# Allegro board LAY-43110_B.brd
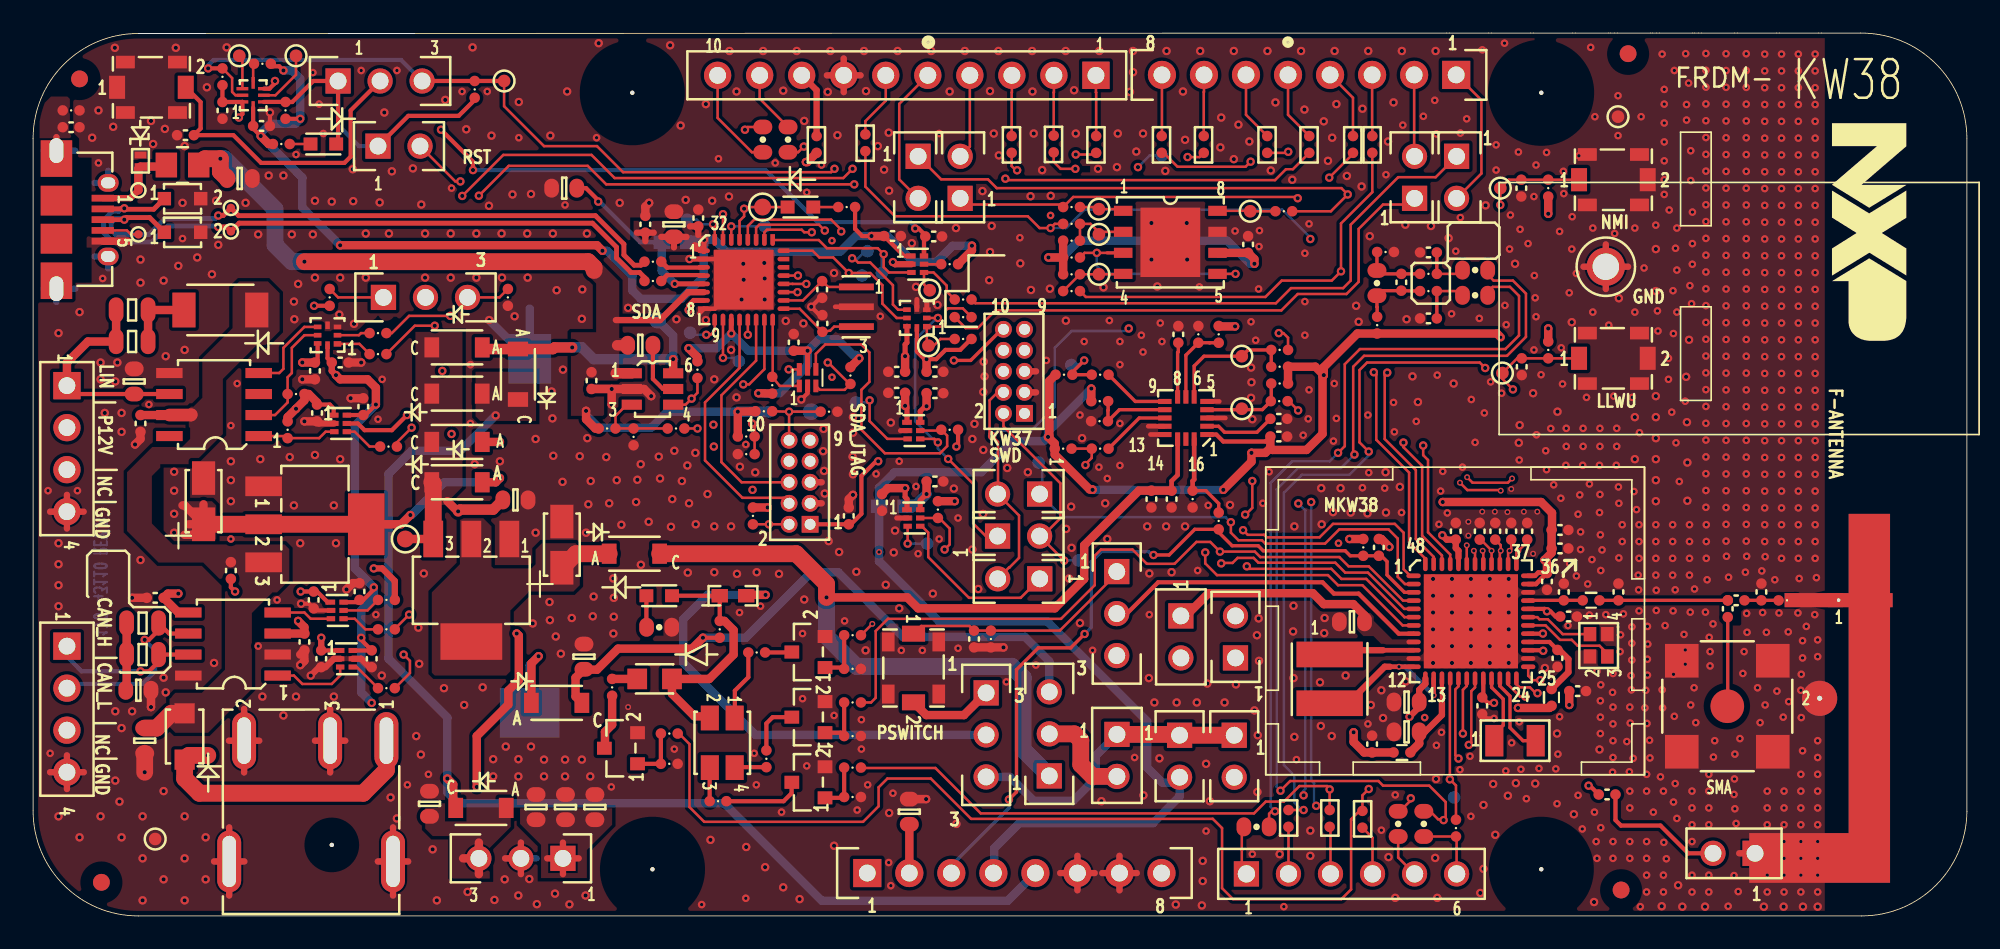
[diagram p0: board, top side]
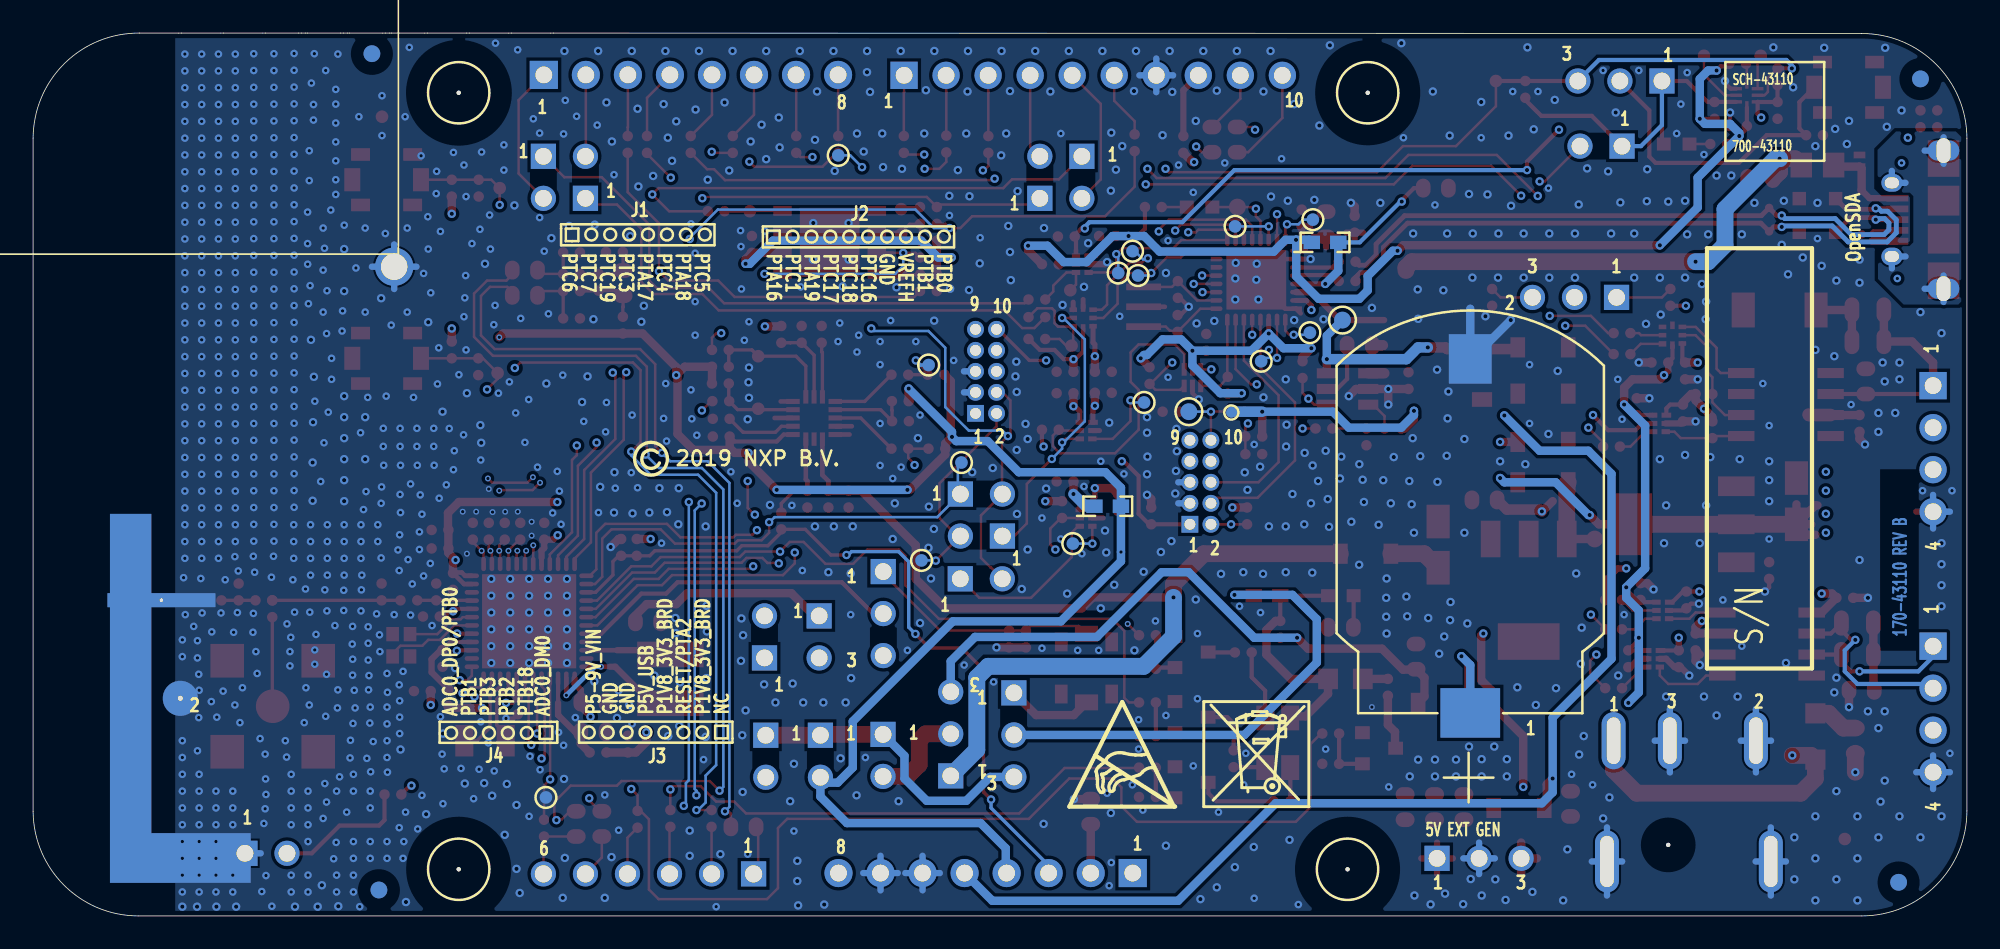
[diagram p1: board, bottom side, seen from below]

Outline 116.85 x 53.37 mm; copper layers: TOP, GND, INT_1, BOTTOM. Coordinates in mm from the lower left corner of the outline.
Outline path: 0,46.99 arc(1.86,51.48) 6.35,53.34 85.41,53.37 arc(85.49,53.37) 85.57,53.36 87.95,53.37 arc(88.03,53.37) 88.11,53.36 90.49,53.37 arc(90.57,53.37) 90.65,53.36 93.03,53.37 arc(93.11,53.37) 93.19,53.36 95.19,53.37 arc(95.24,53.37) 95.3,53.37 95.57,53.37 arc(95.65,53.37) 95.73,53.36 97.73,53.37 arc(97.78,53.37) 97.84,53.37 98.11,53.37 arc(98.19,53.37) 98.27,53.36 100.27,53.37 arc(100.32,53.37) 100.38,53.37 100.65,53.37 arc(100.73,53.37) 100.81,53.36 102.81,53.37 arc(102.89,53.37) 102.97,53.36 105.35,53.37 arc(105.43,53.37) 105.51,53.36 107.89,53.37 arc(107.97,53.37) 108.05,53.36 110.43,53.37 arc(114.96,51.53) 116.85,47.02 116.85,6.3 arc(114.97,1.84) 110.5,0 6.35,0 arc(1.86,1.86) 0,6.35 0,46.99

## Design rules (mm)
constraint set DEFAULT: min track width 0.152
net group DIFFPAIR0: nets SDA_USB_CONN_DN SDA_USB_CONN_DP
net group GA[0:7]: nets N21328439 N21328458
net group USB_SI_D: nets SDA_USB_DN SDA_USB_DP
net group CLOCKS: nets SDA_EXTAL SWD_CLK_TGTMCU SWD_CLK_TGTMCU_BUF
net group POW: nets P5V0_SDA_USB_CONN_VBUS
nets with their own width: min track width 0.254; nets GND
nets with their own width: min track width 0.508; nets P3V3_SDA P5-9V_VIN P5-9V_VIN_VR

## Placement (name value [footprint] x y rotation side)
ANT1  F_Antenna  [F_ANTENNA_DIG528-2]  109.1 19.09 270 top
BT1  S8421-45R  [BATTERY_HOLDER_2032_SM]  30.01 25.17 180 bottom
C1  0.1uF  [CC0402_25]  11.44 48.69 270 top
C2  1000pF  [CC0402_25]  2.3 47.68 0 top
C3  0.1uF  [CC0402_25]  13.8 47.75 0 top
C4  1000pF  [CC0402_25]  9.21 47.19 180 top
C5  10uF  [CC0603_OV]  12.48 44.58 0 top
C6  2.2uF  [CC0603_OV]  32.09 43.99 180 top
C7  1000pF  [CC0402_25]  89.93 43.99 270 top
C8  0.1uF  [CC0402_25]  40.2 42.19 90 top
C9  0.1uF  [CC0402_25]  37 41.81 90 top
C10  10uF  [CC0603_OV]  38.72 41.81 90 top
C11  0.1uF  [CC0402_25]  51.93 41.1 0 top
C12  0.1uF  [CC0402_25]  54.42 41.07 0 top
C13  0.1uF  [CC0402_25]  73.42 40.59 90 top
C14  220PF  [CC0402_25]  84.32 40.11 180 top
C15  0.1uF  [CC0402_25]  82.68 38.3 90 top
C16  22PF  [CC0402_25]  47.68 37.86 270 top
C17  220PF  [CC0402_25]  84.32 36.12 180 top
C18  22PF  [CC0402_25]  47.7 35.81 90 top
C19  0.1uF  [CC0402_25]  69.2 35.15 90 top
C20  0.1uF  [CC0402_25]  45.96 34.67 90 top
C21  18PF  [CC0603_OV]  36.69 34.49 0 top
C22  0.1uF  [CC0402_25]  18.55 33.45 0 top
C23  1000pF  [CC0402_25]  89.95 33.2 270 top
C24  0.1uF  [CC0402_25]  17.03 32.94 270 top
C25  0.1uF  [CC0402_25]  52.18 32.89 180 top
C26  0.1uF  [CC0402_25]  54.5 32.89 0 top
C27  0.1uF  [CC0402_25]  33.74 32.36 270 top
C28  220PF  [CC0603_OV]  6.11 32.31 90 top
C29  0.1uF  [CC0402_25]  52.18 31.62 180 top
C30  0.1uF  [CC0402_25]  54.5 31.6 0 top
C31  0.1uF  [CC0402_25]  19.95 30.78 90 top
C32  0.1uF  [CC0402_25]  17.16 30.4 270 top
C33  0.1uF  [CC0402_25]  6.49 29.77 270 top
C34  0.1uF  [CC0402_25]  75.27 30.05 0 top
C35  0.1uF  [CC0402_25]  75.27 28.98 0 top
C36  0.1uF  [CC0402_25]  56.86 16.74 270 top
C37  0.1uF  [CC0402_25]  54.5 26.26 0 top
C38  4.7uF  [CC0402_25]  67.58 25.2 270 top
C39  0.1uF  [CC0402_25]  68.8 25.2 270 top
C40  10uF  [CC0603_OV]  29.15 25.15 0 top
C41  10UF  [CC3216]  10.3 25.07 90 top
C42  0.1uF  [CC0402_25]  51.3 24.99 270 top
C43  0.1uF  [CC0402_25]  49.29 24.18 90 top
C44  0.1uF  [CC0402_25]  85.97 23.25 90 top
C45  10UF  [CC3216]  31.95 22.44 90 top
C46  12PF  [CC0402_25]  91.48 20.22 270 top
C47  0.1uF  [CC0402_25]  81.32 22.28 90 top
C48  0.1uF  [CC0402_25]  11.95 20.88 270 top
C49  0.1uF  [CC0402_25]  19.72 19.61 90 top
C50  0.6pF  [CC0402_25]  92.49 19.58 90 top
C51  0.3pF  [CC0402_25]  95.8 19.58 90 top
C52  10PF  [CC0402_25]  104.43 19.58 90 top
C53  0.1uF  [CC0402_25]  7.38 19.23 180 top
C54  0.1uF  [CC0402_25]  16.95 19.1 270 top
C55  10PF  [CC0402_25]  102.91 19.08 0 top
C56  10uF  [CC0603_OV]  33.29 15.67 90 top
C57  10PF  [CC0402_25]  102.4 18.57 270 top
C58  10uF  [CC0603_OV]  79.69 17.78 180 top
C59  0.1uF  [CC0402_25]  16.4 16.56 270 top
C60  0.1uF  [CC0402_25]  93.33 13.59 0 top
C61  0.1uF  [CC0402_25]  17.41 15.54 270 top
C62  0.1uF  [CC0402_25]  20.46 15.54 270 top
C63  4700PF  [CC0603_OV]  6.36 13.64 180 top
C64  10uF  [CC0603_OV]  82.99 12.93 180 top
C65  0.1uF  [CC0402_25]  87.57 12.7 270 top
C66  10uF  [CC0603_OV]  82.99 11.13 180 top
C67  1uF  [CC0402_25]  80.91 10.39 90 top
C68  10uF  [CC0603_OV]  6.74 10.59 270 top
C69  1uF  [CC0402_25]  92.11 15.57 270 top
C70  10PF  [CC0402_25]  95.11 7.34 180 top
C71  10uF  [CC0603_OV]  23.95 6.78 90 top
C72  10uF  [CC0603_OV]  30.39 6.58 90 top
C73  10uF  [CC0603_OV]  32.17 6.58 90 top
C74  10uF  [CC0603_OV]  33.95 6.58 90 top
C75  2.2uF  [CC0603_OV]  52.95 6.3 90 top
C78  12PF  [CC0402_25]  92.79 18.1 0 top
C79  3pF  [CC0402_25]  90.28 23.25 90 top
C80  3pF  [CC0402_25]  89.32 23.25 90 top
C81  3pF  [CC0402_25]  88.35 23.25 90 top
C82  3pF  [CC0402_25]  87.41 23.25 90 top
C86  1uF  [CC0402_25]  92.27 23.33 0 top
C87  0.1uF  [CC0402_25]  92.27 22.21 0 top
D1  YEL-GRN  [LED_0603]  46.37 42.85 180 top
D2  PMEG3050EP  [SOD-128]  11.32 36.63 180 top
D3  RB160M-30  [PMDU_SOD123]  25.62 34.37 0 top
D4  RB160M-30  [PMDU_SOD123]  29.3 32.74 90 top
D5  RB160M-30  [PMDU_SOD123]  25.62 31.57 0 top
D6  RB160M-30  [PMDU_SOD123]  25.62 28.65 0 top
D8  RB160M-30  [PMDU_SOD123]  36.33 21.89 180 top
D10  RB160M-30  [PMDU_SOD123]  31.64 12.88 180 top
D11  PNS40010ER  [SOD123W]  9.16 10.85 270 top
D12  RB160M-30  [PMDU_SOD123]  27.06 6.53 0 top
D13  RB160M-30  [PMDU_SOD123]  25.62 26.21 0 top
D14  PESD5V0S1UL  [SOD-882]  6.49 45.64 90 top
D15  PESD5V0S1BA  [SOD323_BID]  9.03 41.33 0 top
D16  PESD5V0S1BA  [SOD323_BID]  9.03 43.36 0 top
J1  SKT_1X8  [CON_1X8_SKT_2P54_TH]  85.99 50.84 270 top
J2  SKT_1X10  [CON_SKT1X10_TH]  64.22 50.81 270 top
J3  SKT_1X8  [CON_1X8_SKT_2P54_TH]  50.41 2.59 90 top
J4  SKT_1X6  [CON_SKT1X6_TH]  73.32 2.54 90 top
J5  HDR_1X3  [HDR103]  18.43 50.47 90 top
J6  HDR 1X2 TH  [SH_HDR102_BOTTOM]  20.84 46.53 90 top
J7  HDR 1X2 TH  [SH_HDR102_BOTTOM]  53.48 45.92 0 top
J8  HDR 1X2 TH  [SH_HDR102_BOTTOM]  86.02 45.92 0 top
J9  HDR 1X2 TH  [SH_HDR102_BOTTOM]  56.02 43.38 180 top
J10  HDR 1X2 TH  [SH_HDR102_BOTTOM]  83.48 43.38 180 top
J11  USB AB 5  [CON9_MICROAB_USB_SHELL_TH]  1.41 42.09 270 top
J12  HDR 2X5  [HDR_2X5_6X3_1P27MM_TH]  59.91 30.38 90 top
J13  HDR 1X4 RA  [CON_HDR_4M_100_TH_RA]  2.04 32.05 270 top
J14  HDR 2X5  [HDR_2X5_6X3_1P27MM_TH]  46.95 23.67 90 top
J15  HDR 1X2 TH  [SH_HDR102_BOTTOM]  60.82 25.5 270 top
J16  HDR 1X2 TH  [SH_HDR102_BOTTOM]  58.28 22.96 90 top
J17  HDR 1X2 TH  [SH_HDR102_BOTTOM]  60.83 20.38 270 top
J21  SLE-100010072-F01  [CON5_SMA_7SQ_SM]  102.37 12.67 0 top
J23  HDR 1X4 RA  [CON_HDR_4M_100_TH_RA]  2.04 16.31 270 top
J24  HDR_1X3  [HDR103]  57.59 13.48 0 top
J27  HDR_1X2  [HDR_1X2_2P54MM]  65.49 10.97 0 top
J28  HDR 1X2 TH  [SH_HDR102_BOTTOM]  69.28 10.92 0 top
J29  HDR 1X2 TH  [SH_HDR102_BOTTOM]  72.58 10.92 0 top
J30  HDR_1X2  [HDR_1X2_2P54MM]  69.35 18.14 0 top
J31  HDR 1X2 TH  [SH_HDR102_BOTTOM]  72.66 15.6 180 top
J32  CON PWR 3  [CON3_PWR_JACK_TH_PJ051A]  21.35 10.59 90 top
J33  HDR_1X2  [HDR_1X2_2P54MM]  104.05 3.78 270 top
J34  HDR_1X3  [HDR103]  32.02 3.48 270 top
J35  HDR_1X3  [HDR103]  61.4 8.46 180 top
J38  HDR_1X3  [HDR103]  65.48 20.82 0 top
J39  HDR_1X3  [HDR103]  21.17 37.39 90 top
L1  330 OHM  [IND_0805]  9.03 45.39 0 top
L2  0.0047uH  [IND_0402]  94.15 19.08 0 top
L3  10uH  [IND_VLS4012E]  78.34 14.33 270 top
L4  0.1uH  [IND_0402]  91.76 13.21 90 top
L5  0.1uH  [IND_0402]  82.72 9.88 180 top
LED1  RED  [LED_0603]  17.54 46.66 0 top
LED2  YEL-GRN  [LED_0603]  37.83 19.35 180 top
LED3  RED  [LED_2P_0805]  37.55 14.33 0 top
LED4  CLV1A-FKB-CK1vw1de1BB7C3C3  [LED4_3P4X3MM_SMT]  41.64 10.46 0 top
NOREF  -  []  49.09 55.07 90 top
NOREF#2  -  []  91.35 15.56 90 top
NOREF#3  -  []  84.5 14.31 0 top
NOREF#4  -  []  101.87 1.95 90 top
NOREF#5  -  []  71.16 28.6 90 top
NOREF#6  -  []  84.65 15.06 0 top
NOREF#7  -  []  86.5 16.31 90 top
NOREF#8  -  []  5 48.44 0 top
NOREF#9  -  []  85.4 59.9 90 top
NOREF#10  -  []  76.57 12.28 90 top
NOREF#11  -  []  365.6 -149.21 0 top
NOREF#12  -  []  93.42 33.71 0 top
NOREF#13  -  []  42.75 10.35 90 top
NOREF#14  -  []  96.14 9.48 0 top
NOREF#15  -  []  102.64 10.48 90 top
NOREF#16  -  []  91.35 15.06 90 top
NOREF#17  -  []  91.35 15.06 90 top
NOREF#18  -  []  37.1 3.48 0 top
NOREF#19  -  []  59.98 38.09 90 top
NOREF#20  -  []  53.58 12.49 90 top
NOREF#21  -  []  78.24 12.86 90 top
NOREF#22  -  []  86.5 17.31 90 top
NOREF#23  -  []  97.14 10.48 0 top
NOREF#24  -  []  26.7 49.62 90 top
NOREF#25  -  []  46.95 23.67 90 top
NOREF#26  -  []  51.68 13.41 0 top
NOREF#27  -  []  46.49 0.94 90 top
NOREF#28  -  []  86.96 43.48 90 top
NOREF#29  -  []  39.17 24.31 90 top
NOREF#30  -  []  52.16 43.48 0 top
NOREF#31  -  []  93.42 39.42 0 top
NOREF#32  -  []  86.25 14.46 0 top
NOREF#33  -  []  76.19 12.66 0 top
NOREF#34  -  []  35.17 24.31 0 top
NOREF#35  -  []  46.24 19.2 0 top
NOREF#36  -  []  20.44 25.64 0 top
NOREF#37  -  []  21.49 25.64 90 top
NOREF#38  -  []  91.5 14.31 90 top
NOREF#39  -  []  46.95 23.67 90 top
NOREF#40  -  []  11.19 19.95 0 top
NOREF#41  -  []  54.85 9.54 90 top
NOREF#42  -  []  97.07 37.9 90 top
NOREF#43  -  []  173.86 59.85 0 top
NOREF#44  -  []  84.65 15.06 0 top
NOREF#45  -  []  69.66 31.37 0 top
NOREF#46  -  []  14.49 15.45 90 top
NOREF#47  -  []  85.4 59.9 0 top
NOREF#48  -  []  93.92 37.9 0 top
NOREF#49  -  []  -14.33 -140.12 90 top
NOREF#50  -  []  37.1 3.48 0 top
NOREF#51  -  []  26.94 3.48 0 top
NOREF#52  -  []  93.92 32.18 0 top
NOREF#53  -  []  86.63 21.27 0 top
NOREF#54  -  []  86.88 17.81 0 top
NOREF#55  -  []  48.22 55.07 0 top
NOREF#56  -  []  11.04 20.75 0 top
NOREF#57  -  []  83.1 44.9 90 top
NOREF#58  -  []  92.8 0.01 90 top
NOREF#59  -  []  27.13 49.52 90 top
NOREF#60  -  []  20.53 25.86 0 top
NOREF#61  -  []  6.18 44.51 90 top
NOREF#62  -  []  93.34 32.06 0 top
NOREF#63  -  []  85.93 31.51 0 top
NOREF#64  -  []  17.02 47.69 90 top
NOREF#65  -  []  86.25 14.46 0 top
NOREF#66  -  []  25.52 9.32 90 top
NOREF#67  -  []  59.91 30.38 90 top
NOREF#68  -  []  390.58 -149.21 0 top
NOREF#69  -  []  85.25 14.46 0 top
NOREF#70  -  []  48.13 54.85 0 top
NOREF#71  -  []  68.16 28.6 0 top
NOREF#72  -  []  30.01 12.27 90 top
NOREF#73  -  []  40.14 3.62 0 top
NOREF#74  -  []  93.17 64.32 0 top
NOREF#75  -  []  52.84 15.13 90 top
NOREF#76  -  []  90.38 14.31 90 top
NOREF#77  -  []  68.16 28.61 0 top
NOREF#78  -  []  97.07 32.18 90 top
NOREF#79  -  []  23.41 12.43 90 top
NOREF#80  -  [unnamed#2]  4.13 2.03 90 top
NOREF#81  -  []  50.55 9.54 0 top
NOREF#82  -  []  85.64 44.91 90 top
NOREF#83  -  []  24.2 10.74 90 top
NOREF#84  -  []  93.44 44.98 0 top
NOREF#85  -  []  102.29 7.46 0 top
NOREF#86  -  []  83.42 17.56 90 top
NOREF#87  -  []  35.42 25.81 0 top
NOREF#88  -  []  27.15 49.84 90 top
NOREF#89  -  []  87.06 38.09 90 top
NOREF#90  -  []  97.67 43.33 90 top
NOREF#91  -  []  0 41.92 0 top
NOREF#92  -  []  93.34 32.06 0 top
NOREF#93  -  []  85.25 14.46 0 top
NOREF#94  -  []  68.38 29.1 90 top
NOREF#95  -  []  14.64 15.15 90 top
NOREF#96  -  []  13.14 48.82 90 top
NOREF#97  -  []  44.07 3.54 0 top
NOREF#98  -  []  93.37 43.33 0 top
NOREF#99  -  []  70.93 31.1 90 top
NOREF#100  -  []  6.49 45.29 90 top
NOREF#101  -  []  97.64 32.06 90 top
NOREF#102  -  []  9.3 48.44 90 top
NOREF#103  -  []  86.5 16.31 90 top
NOREF#104  -  []  95.07 61.52 90 top
NOREF#105  -  []  -14.33 -113.45 0 top
NOREF#106  -  []  9.49 50.34 0 top
NOREF#107  -  []  30.01 12.43 90 top
NOREF#108  -  []  47.92 22.91 0 top
NOREF#109  -  []  53.2 12.91 90 top
NOREF#110  -  []  97.07 32.18 90 top
NOREF#111  -  []  90.75 14.46 90 top
NOREF#112  -  []  86.5 17.31 90 top
NOREF#113  -  [unnamed#2]  96.38 52.12 90 top
NOREF#114  -  []  6.18 44.51 0 top
NOREF#115  -  []  13.72 51.99 0 top
NOREF#116  -  []  49.18 54.85 90 top
NOREF#117  -  []  97.09 43.46 90 top
NOREF#118  -  []  22.11 17.16 0 top
NOREF#119  -  []  5.58 48.56 0 top
NOREF#120  -  []  60.87 23.02 90 top
NOREF#121  -  []  44.84 0.36 90 top
NOREF#122  -  []  45.68 23.67 0 top
NOREF#123  -  []  93.94 43.46 0 top
NOREF#124  -  []  101.37 16.29 0 top
NOREF#125  -  []  86.75 59.7 90 top
NOREF#126  -  []  93.42 33.71 0 top
NOREF#127  -  []  60.87 29.62 0 top
NOREF#128  -  []  99.23 1.95 0 top
NOREF#129  -  []  5.89 -36.7 0 top
NOREF#130  -  []  44.12 15.23 90 top
NOREF#131  -  []  108.7 47.9 270 top
NOREF#132  -  []  27.15 50.64 90 top
NOREF#133  -  []  8.73 48.56 90 top
NOREF#134  -  []  58.64 30.38 0 top
NOREF#135  -  []  93.92 42.98 0 top
NOREF#136  -  []  68.38 31.1 0 top
NOREF#137  -  []  93.92 32.18 0 top
NOREF#138  -  []  95.26 6.02 0 top
NOREF#139  -  []  47.92 16.31 90 top
NOREF#140  -  []  -359.49 185.27 0 top
NOREF#141  -  []  21.4 25.86 90 top
NOREF#142  -  []  54.8 43.48 90 top
NOREF#143  -  []  14.49 15.45 90 top
NOREF#144  -  []  -82.26 -259.56 0 top
NOREF#145  -  []  93.42 44.5 0 top
NOREF#146  -  []  97.64 42.85 90 top
NOREF#147  -  []  5.08 50.09 0 top
NOREF#148  -  []  84.42 38.09 0 top
NOREF#149  -  []  52.36 19.2 0 top
NOREF#150  -  []  93.34 42.85 0 top
NOREF#151  -  []  43.19 0.94 0 top
NOREF#152  -  []  97.07 42.98 90 top
NOREF#153  -  []  84.32 43.48 0 top
NOREF#154  -  []  43.59 0.41 0 top
NOREF#155  -  []  46.71 3.54 90 top
NOREF#156  -  []  59.91 30.38 90 top
NOREF#157  -  []  42.8 16.65 90 top
NOREF#158  -  []  22.88 9.32 0 top
NOREF#159  -  []  97.64 32.06 90 top
NOREF#160  -  []  69.16 28.82 90 top
NOREF#161  -  []  51.68 13.41 90 top
NOREF#162  -  []  38.82 10.44 90 top
NOREF#163  -  []  41.48 15.23 0 top
NOREF#164  -  []  50.94 12.49 0 top
NOREF#165  -  []  381.86 -165.18 0 top
NOREF#166  -  []  -385.52 -339.88 0 top
NOREF#167  -  []  103.64 9.48 90 top
NOREF#168  -  []  50.2 15.13 0 top
NOREF#169  -  []  57.34 38.09 0 top
NOREF#170  -  []  30.01 12.27 90 top
NOREF#171  -  [unnamed#2]  2.81 50.6 90 top
NOREF#172  -  []  42.78 3.62 90 top
NOREF#173  -  []  84.5 14.31 0 top
NOREF#174  -  []  93.34 37.77 0 top
NOREF#175  -  []  68.38 30.6 90 top
NOREF#176  -  []  90.75 14.46 90 top
NOREF#177  -  []  56.02 44.9 90 top
NOREF#178  -  []  97.64 37.77 90 top
NOREF#179  -  []  68.38 30.6 90 top
NOREF#180  -  []  9.99 48.82 0 top
NOREF#181  -  []  91.35 15.56 90 top
NOREF#182  -  []  86.88 17.81 90 top
NOREF#183  -  [unnamed#2]  95.96 1.57 90 top
NOREF#184  -  []  86.63 21.27 0 top
NOREF#185  -  []  53.48 44.91 90 top
NOREF#186  -  []  83.38 14.31 0 top
NOREF#187  -  [unnamed#2]  95.96 1.57 90 bottom
NOREF#188  -  [unnamed#2]  4.13 2.03 90 bottom
NOREF#189  -  []  79.51 27.61 180 bottom
NOREF#190  -  []  77.09 5.51 180 bottom
NOREF#191  -  [unnamed#2]  36.21 49.76 180 bottom
NOREF#192  -  []  77.14 12.88 180 bottom
NOREF#193  -  [unnamed#2]  91.14 2.82 180 bottom
NOREF#194  -  [unnamed#2]  96.38 52.12 90 bottom
NOREF#195  -  [unnamed#2]  91.14 49.76 180 bottom
NOREF#196  -  []  128.76 -52.14 270 bottom
NOREF#197  -  [unnamed#2]  37.43 2.82 180 bottom
NOREF#198  -  []  9.36 14.96 90 bottom
NOREF#199  -  []  54.22 6.6 180 bottom
NOREF#200  -  []  46.11 6.6 180 bottom
NOREF#201  -  []  114.3 39.52 180 bottom
NOREF#202  -  [unnamed#2]  2.81 50.6 90 bottom
Q1  BSH111BK  [SOT23_A]  46.85 15.95 90 top
Q2  BSH111BK  [SOT23_A]  46.85 12.01 90 top
Q3  BSH111BK  [SOT23_A]  46.85 8.08 90 top
Q4  BSH111BK  [SOT23_A]  35.52 10.13 90 top
R1  4.7K  [RC0402_25]  13.86 51.51 0 top
R2  180K  [RC0402_25]  11.44 50.72 90 top
R3  0  [RC0402_25]  26.68 49.96 90 top
R4  100  [RC0402_25]  2.3 48.69 0 top
R5  10K  [RC0402_25]  15.25 48.69 90 top
R6  0  [RC0603_OV]  44.09 46.93 90 top
R7  0  [RC0603_OV]  45.62 46.93 90 top
R8  680  [RC0402_25]  15 46.66 0 top
R9  10K  [RC0402_25]  91.55 43.99 90 top
R10  270  [RC0402_25]  49.16 42.85 180 top
R11  0  [RC0402_25]  62.75 42.85 0 top
R12  0  [RC0402_25]  75.58 42.6 0 top
R13  0  [RC0402_25]  62.75 41.83 0 top
R14  10K  [RC0402_25]  62.75 40.82 0 top
R15  4.99K  [RC0402_25]  81.72 40.13 0 top
R16  4.7K  [RC0402_25]  55.38 39.4 180 top
R17  10K  [RC0402_25]  62.75 39.8 0 top
R18  33  [RC0402_25]  37.45 39.55 0 top
R19  0  [RC0603_OV]  87.13 39.04 180 top
R20  100  [RC0402_25]  84.32 38.81 0 top
R21  10K  [RC0402_25]  62.75 38.79 0 top
R22  33  [RC0402_25]  37.45 38.38 0 top
R23  0  [RC0402_25]  62.75 37.77 180 top
R24  100  [RC0402_25]  84.32 37.77 0 top
R25  0  [RC0603_OV]  87.13 37.52 180 top
R26  1K  [RC0402_25]  56.2 37.26 0 top
R27  2K  [RC0805_OV]  5.98 36.63 0 top
R28  0  [RC0402_25]  20.84 35.23 0 top
R29  1K  [RC0402_25]  56.2 36.2 180 top
R30  4.99K  [RC0402_25]  81.22 35.71 90 top
R31  0  [RC0402_25]  70.41 35.15 90 top
R32  10K  [RC0402_25]  71.64 35.15 270 top
R33  10K  [RC0402_25]  56.2 34.87 180 top
R34  2K  [RC0805_OV]  5.98 34.72 0 top
R35  0  [RC0402_25]  20.84 33.96 0 top
R36  10K  [RC0402_25]  91.55 34.21 270 top
R37  0  [RC0402_25]  75.32 34.21 0 top
R38  10K  [RC0402_25]  40.14 33.02 270 top
R39  10.0K  [RC0402_25]  62.29 32.72 0 top
R40  0  [RC0402_25]  64.48 32.72 180 top
R41  2.2K  [RC0402_25]  75.32 33.2 180 top
R42  10K  [RC0402_25]  49.39 32.66 270 top
R43  10K  [RC0402_25]  44.67 32.08 90 top
R44  2.2K  [RC0402_25]  75.32 32.18 180 top
R45  4.7K  [RC0402_25]  15.89 31.55 0 top
R46  10K  [RC0402_25]  64.45 31.12 0 top
R47  0  [RC0402_25]  75.3 31.12 0 top
R48  4.7K  [RC0402_25]  44.16 30.51 0 top
R49  10K  [RC0402_25]  48.09 30.48 0 top
R50  4.7K  [RC0402_25]  17.92 37.39 90 top
R51  0  [RC0402_25]  64.44 29.91 180 top
R52  10.0K  [RC0402_25]  34.68 29.46 0 top
R53  1K  [RC0402_25]  38.85 29.46 180 top
R54  4.7K  [RC0402_25]  15.38 29.39 90 top
R55  4.7K  [RC0402_25]  55.38 29.39 180 top
R56  4.7K  [RC0402_25]  43.09 28.98 0 top
R57  15K  [RC0402_25]  36.28 28.96 270 top
R58  0  [RC0402_25]  21.48 28.37 0 top
R60  10.0K  [RC0402_25]  62.24 28.24 0 top
R61  0  [RC0402_25]  64.48 28.24 180 top
R62  10.0K  [RC0402_25]  43.09 27.91 180 top
R63  102K  [RC0402_25]  57.87 16.74 270 top
R64  10K  [RC0402_25]  70.07 25.2 90 top
R65  4.7K  [RC0402_25]  54.67 24.56 270 top
R66  10K  [RC0402_25]  43.5 24.18 270 top
R67  0  [RC0402_25]  71.64 23.88 270 top
R69  10K  [RC0402_25]  80.38 22.28 270 top
R70  0  [RC0402_25]  41.49 17.32 270 top
R71  4.7K  [RC0402_25]  21.35 19.1 180 top
R72  0  [RC0402_25]  105.98 19.07 0 top
R73  60.4  [RC0805_OV]  6.62 17.7 180 top
R74  0  [RC0402_25]  21.35 17.32 0 top
R75  220  [RC0603_OV]  37.83 17.45 0 top
R76  0  [RC0402_25]  49.52 16.97 180 top
R77  60.4  [RC0805_OV]  6.62 15.8 0 top
R80  10K  [RC0402_25]  49.52 14.94 180 top
R81  0  [RC0402_25]  21.35 13.77 0 top
R82  0  [RC0402_25]  49.52 12.9 0 top
R85  10K  [RC0402_25]  49.52 10.87 0 top
R87  470  [RC0402_25]  43.73 15.93 180 top
R88  270  [RC0402_25]  34.99 13.82 90 top
R89  0  [RC0402_25]  49.52 8.97 0 top
R90  270  [RC0402_25]  44.31 9.5 270 top
R92  0  [RC0402_25]  38.44 11.02 180 top
R93  270  [RC0402_25]  41.39 6.93 180 top
R94  10K  [RC0402_25]  49.52 7.19 180 top
R96  0  [RC0603_OV]  82.49 5.56 270 top
R97  0  [RC0603_OV]  84.04 5.56 270 top
R98  10K  [RC0402_25]  38.44 9.19 180 top
R99  0  [RC0603_OV]  73.93 5.38 180 top
R100  0  [RC0402_25]  85.98 5.31 270 top
R101  4.7K  [RC0402_25]  28.69 37.39 270 top
RT1  10K  [RC0603_OV]  81.2 38.25 90 top
SH1  0  [SH0402]  50.29 46.74 90 top
SH2  0  [SH0402]  61.67 46.66 90 top
SH3  0  [SH0402]  47.35 46.63 90 top
SH4  0  [SH0402]  59.13 46.63 90 top
SH5  0  [SH0402]  64.24 46.63 90 top
SH6  0  [SH0402]  68.2 46.63 90 top
SH7  0  [SH0402]  70.74 46.63 90 top
SH8  0  [SH0402]  74.57 46.63 90 top
SH9  0  [SH0402]  77.11 46.63 90 top
SH10  0  [SH0402]  79.76 46.63 90 top
SH11  0  [SH0402]  80.92 46.63 90 top
SH12  0  [SH0603]  42.29 19.35 0 top
SH13  0  [SH0402]  75.86 5.89 270 top
SH14  0  [SH0402]  78.35 5.89 270 top
SH15  0  [SH0402]  80.33 5.84 270 top
SH16  0  [SH0603]  38.79 40.72 180 bottom
SH17  0  [SH0603]  51.92 24.77 180 bottom
SW1  TL1015AF160QG  [SW2_SPST_4X3_SM]  7.15 50.09 0 top
SW2  TL1015AF160QG  [SW2_SPST_4X3_SM]  95.49 44.5 0 top
SW3  TL1015AF160QG  [SW2_SPST_4X3_SM]  95.49 33.71 0 top
SW4  TL1015AF160QG  [SW2_SPST_4X3_SM]  53.2 14.99 270 top
TP1  -  [TPAD_030]  12.46 51.99 0 top
TP2  -  [TPAD_030]  15.89 51.99 0 top
TP3  -  [TPAD_030]  28.46 50.47 0 top
TP4  -  [TPAD_030]  95.77 48.31 0 top
TP5  -  [TPAD_020]  6.36 43.87 0 top
TP6  -  [TPAD_030]  88.66 43.99 0 top
TP7  -  [TPAD_020]  11.95 42.8 0 top
TP8  -  [TPAD_040]  44.08 42.85 0 top
TP9  -  [TPAD_030]  64.4 42.72 0 top
TP10  -  [TPAD_030]  73.55 42.6 0 top
TP11  -  [TPAD_030]  64.4 41.2 0 top
TP12  -  [TPAD_020]  11.95 41.38 0 top
TP13  -  [TPAD_020]  6.36 41.2 0 top
TP14  -  [TPAD_030]  64.4 38.79 0 top
TP15  -  [TPAD_030]  54.18 37.82 0 top
TP16  -  [TPAD_030]  54.1 34.47 0 top
TP17  -  [TPAD_030]  73.04 33.83 0 top
TP18  -  [TPAD_030]  88.79 32.82 0 top
TP19  TESTLOOP_BLACK  [TP_TH_063]  95.03 39.24 0 top
TP20  -  [TPAD_030]  73.04 30.66 0 top
TP21  -  [TPAD_040]  22.49 22.78 0 top
TP22  -  [TPAD_030]  68.2 45.97 180 bottom
TP23  -  [TPAD_030]  39.52 42.09 180 bottom
TP24  -  [TPAD_030]  44.22 41.68 180 bottom
TP25  -  [TPAD_030]  85.86 7.16 180 bottom
TP26  -  [TPAD_030]  50.09 38.71 180 bottom
TP27  -  [TPAD_030]  51.28 38.86 180 bottom
TP28  -  [TPAD_030]  50.42 40.18 180 bottom
TP29  -  [TPAD_040]  37.73 36.02 180 bottom
TP30  -  [TPAD_030]  39.7 35.26 180 bottom
TP31  -  [TPAD_030]  42.65 33.53 180 bottom
TP32  -  [TPAD_030]  62.74 33.3 180 bottom
TP33  -  [TPAD_030]  49.72 31.04 180 bottom
TP34  -  [TPAD_040]  47.02 30.48 180 bottom
TP35  -  [TPAD_020]  44.45 30.43 180 bottom
TP36  -  [TPAD_030]  60.76 27.41 180 bottom
TP37  -  [TPAD_030]  54.03 22.5 180 bottom
TP38  -  [TPAD_030]  63.17 21.49 180 bottom
TP39  -  [TPAD_030]  7.38 4.65 0 top
U1  NTSX2102GU8H  [XQFN8_1P45X1P25MM]  13.3 49.61 90 top
U3  AT45DB041E  [DFN8_1P27_6X5MM_3P6X4P2]  68.72 40.72 0 top
U4  74LVCH1T45  [UDFN6_1X1P5MM]  53.45 39.4 0 top
U5  MK20DX128VFM5  [QFN32_S142EP]  42.94 38.46 0 top
U6  74LVC2T45GM,125  [QFN8_1P6X1P6MM]  53.4 36.14 180 top
U7  74LVC2T45GM,125  [QFN8_1P6X1P6MM]  17.79 35.1 180 top
U8  NLX2G14  [UDFN6_1P45X1_0P5MM]  46.8 32.54 90 top
U9  MIC2005-0.8YM6  [SOT23-6_A]  37.43 31.85 0 top
U10  TJA1027T/20  [SO8_1P27_4X5]  10.93 30.91 180 top
U11  FXOS8700CQ  [QFN5X3_0P5_3X3]  69.66 30.1 180 top
U12  74LVCH1T45  [UDFN6_1X1P5MM]  18.58 29.77 0 top
U13  74LVCH1T45  [UDFN6_1X1P5MM]  53.23 29.34 0 top
U14  74LVCH1T45  [UDFN6_1X1P5MM]  53.23 24.05 0 top
U15  NCP1117ST50T3G  [SOT223]  17.03 23.67 270 top
U16  NCP1117ST33T3G  [SOT223]  26.48 19.69 180 top
U17  74LVCH1T45  [UDFN6_1X1P5MM]  18.38 18.47 0 top
U18  MKW38A512VFT4  [QFN_48_0P5_7X7_5P7EP]  86.88 17.81 0 top
U19  TJA1057GT/3  [SO8_1P27_4X5]  12.08 16.43 180 top
U20  74LVCH1T45  [UDFN6_1X1P5MM]  18.94 15.54 0 top
X1  8 MHz  [XTAL3_3P35X1P45_SM]  49.75 36.82 90 top
Y1  32MHz  [XTAL4_2P1X1P7MM_SM]  94.6 16.36 270 top
Y2  32.768 KHZ  [XTAL2-3P2X1P5-SM]  89.55 10.59 0 top

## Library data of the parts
ANT1 = F_Antenna
BT1 = BATTERY
C1-C20 C22-C40 C42-C44 C46-C51 C53 C54 C56 C58-C69 C71-C75 C78-C82 C86 C87 = CAP_NP
C21 C52 C55 C57 C70 = CAP_NP: tolerance: 5%
C41 C45 = CAP_POL
D1 LED1-LED3 = LED
D2-D6 D8 D10 D12 D13 = DIODE_SCHTKY
D11 = DIODE
D14 = DIODE_TVS
D15 D16 = DIODE_TVS_BIDIR
J1 J3 = CONN_HDR_8X1
J2 = CONN_HDR_10X1
J4 = CONN_HDR_6X1
J5 J24 J34 J35 J38 J39 = CONN_HDR_3X1
J6-J10 J15-J17 J27-J31 J33 = CONN_HDR_2X1
J11 = MICRO_USB_CONN_9PIN
J12 J14 = CONN_HDR_5X2
J13 J23 = CONN_HDR_4X1
J21 = CONN_COAX_1P_F
J32 = DC_POWER_JACK_SHD
L1 = BEAD
L2 L4 L5 = INDUCTOR
L3 = IND_FERRITE
LED4 = CLV1A_LED_4P
Q1-Q4 = NMOS_2N7002BKW_3P
R1 R9 R16 R20 R21 R24 R36 R39 R45 R48 R50 R52 R54-R56 R60 R65 R71 R101 = RES: tolerance: 1%
R2 R4-R8 R10-R15 R17-R19 R22 R23 R25-R35 R37 R38 R40-R44 R46 R47 R49 R51 R53 R57 R58 R61-R64 R66 R67 R69 R70 R72-R77 R80-R82 R85 R87-R90 R92-R94 R96-R100 = RES
R3 = RES: tolerance: 5%
RT1 = THERMISTOR: tolerance: 1%
SH1-SH17 = RES_SHORT-2
SW1-SW4 = SW_SPNO_2P_GND6P
TP1-TP39 = TESTLOOP
U1 = NTSX2102GD
U3 = AT45DB021E_9P
U4 U12-U14 U17 U20 = 74LVCH1T45_6P
U5 = PK20DX128V_QFN_32P
U6 U7 = 74LVC2T45GM_8P
U8 = NLX2G14_6P
U9 = MIC2005-0.8YM6
U10 = TJA1027T_8P
U11 = FXOS8700CQ_QFN_16P
U15 U16 = LD1117AS18
U18 = MKW38A512VFT4_QFN48
U19 = TJA1057GT3_8P
X1 = XTAL_CS
Y1 = XTAL_13
Y2 = XTAL

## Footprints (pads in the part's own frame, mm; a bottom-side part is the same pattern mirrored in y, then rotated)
BATTERY_HOLDER_2032_SM
  rect 3.607x2.997 smd: 1(0,-12.9)
  rect 2.591x2.997 smd: 2(0,8.5)
CC0402_25
  round 0.635 smd: 1(-0.508,0) 2(0.508,0)
CC0603_OV
  oval 0.889x1.143 smd: 1(-0.762,0) 2(0.762,0)
CC3216
  rect 2.032x1.397 smd: 1(-1.397,0) 2(1.397,0)
CON3_PWR_JACK_TH_PJ051A
  round 0.254 hole 2.54 unplated: (-6.3,3.3)
  oval 3.454x1.448 hole 2.819x0.813: 1(0,0) 2(0,8.6) 3(0,3.4)
  oval 3.734x1.448 hole 3.099x0.813: SH1(-7.3,9.5) SH2(-7.3,-0.4)
CON5_SMA_7SQ_SM
  round 2.032 smd: 1(0,0)
  rect 2.032x2.032 smd: 2(-2.75,-2.75) 3(2.75,-2.75) 4(2.75,2.75) 5(-2.75,2.75)
CON9_MICROAB_USB_SHELL_TH
  rect 1.803x1.905 smd: (-1.15,0) (1.15,0)
  rect 0.406x1.346 smd: 1(-1.3,2.8) 2(-0.65,2.8) 3(0,2.8) 4(0.65,2.8) 5(1.3,2.8)
  oval 1.067x1.27 hole 0.66x0.864: 6(2.225,3.125) 9(-2.225,3.125)
  rect 2.21x1.905 hole 1.499x0.838: 7(4.175,0) 8(-4.175,0)
CON_1X8_SKT_2P54_TH
  rect 1.702x1.702 hole 1.016: 1(0,0)
  round 1.702 hole 1.016: 2(0,-2.54) 3(0,-5.08) 4(0,-7.62) 5(0,-10.16) 6(0,-12.7) 7(0,-15.24) 8(0,-17.78)
CON_HDR_4M_100_TH_RA
  rect 1.651x1.651 hole 1.016: 1(0,0)
  round 1.651 hole 1.016: 2(2.54,0) 3(5.08,0) 4(7.62,0)
CON_SKT1X6_TH
  rect 1.524x1.524 hole 1.041: 1(0,0)
  round 1.524 hole 1.041: 2(0,-2.54) 3(0,-5.08) 4(0,-7.62) 5(0,-10.16) 6(0,-12.7)
CON_SKT1X10_TH
  rect 1.651x1.651 hole 1.016: 1(0,0)
  round 1.651 hole 1.016: 2(0,-2.54) 3(0,-5.08) 4(0,-7.62) 5(0,-10.16) 6(0,-12.7) 7(0,-15.24) 8(0,-17.78) 9(0,-20.32) 10(0,-22.86)
DFN8_1P27_6X5MM_3P6X4P2
  rect 1.118x0.61 smd: 1(-2.85,1.905) 2(-2.85,0.635) 3(-2.85,-0.635) 4(-2.85,-1.905) 5(2.85,-1.905) 6(2.85,-0.635) 7(2.85,0.635) 8(2.85,1.905)
  rect 3.607x4.191 smd: 9(0,0)
F_ANTENNA_DIG528-2
  custom 0.212x0.212 hole 0.305: 1(0,0)
  custom 2.127x2.127 hole 0.305: 2(5.933,-1.144)
HDR103
  rect 1.524x1.524 hole 1.016: 1(0,0)
  round 1.524 hole 1.016: 2(0,-2.54) 3(0,-5.08)
HDR_1X2_2P54MM
  rect 1.524x1.524 hole 1.016: 1(0,0)
  round 1.524 hole 1.016: 2(0,-2.54)
HDR_2X5_6X3_1P27MM_TH
  rect 1.016x1.016 hole 0.66: 1(0,0)
  round 1.016 hole 0.66: 2(0,1.27) 3(1.27,0) 4(1.27,1.27) 5(2.54,0) 6(2.54,1.27) 7(3.81,0) 8(3.81,1.27) 9(5.08,0) 10(5.08,1.27)
IND_0402
  round 0.635 smd: 1(-0.508,0) 2(0.508,0)
IND_0805
  rect 1.295x1.499 smd: 1(-0.978,0) 2(0.978,0)
IND_VLS4012E
  rect 1.549x4.013 smd: 1(-1.475,0) 2(1.475,0)
LED4_3P4X3MM_SMT
  rect 1.092x1.499 smd: 1(0.75,1.5) 2(-0.75,1.5) 3(-0.75,-1.5) 4(0.75,-1.5)
LED_2P_0805
  rect 1.194x1.245 smd: A(1.05,0) C(-1.05,0)
LED_0603
  rect 0.838x0.787 smd: A(-0.775,0) C(0.775,0)
PMDU_SOD123
  rect 0.889x1.219 smd: A(1.525,0) C(-1.525,0)
QFN5X3_0P5_3X3
  rect 0.813x0.305 smd: 1(-1.275,1) 2(-1.275,0.5) 3(-1.275,0) 4(-1.275,-0.5) 5(-1.275,-1) 9(1.275,-1) 10(1.275,-0.5) 11(1.275,0) 12(1.275,0.5) 13(1.275,1)
  rect 0.305x0.813 smd: 6(-0.5,-1.275) 7(0,-1.275) 8(0.5,-1.275) 14(0.5,1.275) 15(0,1.275) 16(-0.5,1.275)
QFN8_1P6X1P6MM
  rect 0.457x0.33 smd: 1(-0.6,0.525)
  rect 0.457x0.279 smd: 2(-0.6,0) 3(-0.6,-0.5) 5(0.6,-0.5) 6(0.6,0) 7(0.6,0.5)
  rect 0.279x0.457 smd: 4(0,-0.6) 8(0,0.6)
QFN32_S142EP
  custom 0.07x0.07 smd: 1(-2.4,1.751) 2(-2.4,1.251) 3(-2.4,0.751) 4(-2.4,0.25) 5(-2.4,-0.25) 6(-2.4,-0.751) 7(-2.4,-1.251) 8(-2.4,-1.751) 9(-1.751,-2.4) 10(-1.251,-2.4) 11(-0.751,-2.4) 12(-0.25,-2.4) 13(0.25,-2.4) 14(0.751,-2.4) 15(1.251,-2.4) 16(1.751,-2.4) 17(2.4,-1.751) 18(2.4,-1.251) 19(2.4,-0.751) 20(2.4,-0.25) 21(2.4,0.25) 22(2.4,0.751) 23(2.4,1.251) 24(2.4,1.751) 25(1.751,2.4) 26(1.251,2.4) 27(0.751,2.4) 28(0.25,2.4) 29(-0.25,2.4) 30(-0.751,2.4) 31(-1.251,2.4) 32(-1.751,2.4)
  rect 3.607x3.607 smd: 33(0,0)
QFN_48_0P5_7X7_5P7EP
  oval 0.864x0.279 smd: 1(-3.463,2.75) 2(-3.463,2.25) 3(-3.463,1.75) 4(-3.463,1.25) 5(-3.463,0.75) 6(-3.463,0.25) 7(-3.463,-0.25) 8(-3.463,-0.75) 9(-3.463,-1.25) 10(-3.463,-1.75) 11(-3.463,-2.25) 12(-3.463,-2.75) 25(3.463,-2.75) 26(3.463,-2.25) 27(3.463,-1.75) 28(3.463,-1.25) 29(3.463,-0.75) 30(3.463,-0.25) 31(3.463,0.25) 32(3.463,0.75) 33(3.463,1.25) 34(3.463,1.75) 35(3.463,2.25) 36(3.463,2.75)
  oval 0.279x0.864 smd: 13(-2.75,-3.463) 14(-2.25,-3.463) 15(-1.75,-3.463) 16(-1.25,-3.463) 17(-0.75,-3.463) 18(-0.25,-3.463) 19(0.25,-3.463) 20(0.75,-3.463) 21(1.25,-3.463) 22(1.75,-3.463) 23(2.25,-3.463) 24(2.75,-3.463) 37(2.75,3.463) 38(2.25,3.463) 39(1.75,3.463) 40(1.25,3.463) 41(0.75,3.463) 42(0.25,3.463) 43(-0.25,3.463) 44(-0.75,3.463) 45(-1.25,3.463) 46(-1.75,3.463) 47(-2.25,3.463) 48(-2.75,3.463)
  rect 5.69x5.69 smd: 49(0,0)
RC0402_25
  round 0.635 smd: 1(-0.508,0) 2(0.508,0)
RC0603_OV
  oval 0.889x1.143 smd: 1(-0.762,0) 2(0.762,0)
RC0805_OV
  oval 0.889x1.524 smd: 1(-0.965,0) 2(0.965,0)
SH0402
  round 0.635 smd: 1(-0.508,0) 2(0.508,0)
SH0603
  rect 0.991x0.813 smd: 1(-0.8,0) 2(0.8,0)
SH_HDR102_BOTTOM
  rect 1.524x1.524 hole 1.016: 1(0,0)
  round 1.524 hole 1.016: 2(0,-2.54)
SO8_1P27_4X5
  rect 1.6x0.61 smd: 1(-2.7,1.905) 2(-2.7,0.635) 3(-2.7,-0.635) 4(-2.7,-1.905) 5(2.7,-1.905) 6(2.7,-0.635) 7(2.7,0.635) 8(2.7,1.905)
SOD123W
  rect 1.219x1.219 smd: A(1.4,0) C(-1.4,0)
SOD323_BID
  rect 0.813x0.813 smd: 1(-1.1,0) 2(1.1,0)
SOD-128
  rect 1.397x2.108 smd: A(-2.2,0) C(2.2,0)
SOD-882
  rect 0.406x0.711 smd: A(0.35,0) C(-0.35,0)
SOT23-6_A
  rect 1.219x0.61 smd: 1(-1.25,0.95) 2(-1.25,0) 3(-1.25,-0.95) 4(1.25,-0.95) 5(1.25,0) 6(1.25,0.95)
SOT23_A
  rect 0.787x0.889 smd: 1(-0.94,-1.003) 2(0.94,-1.003) 3(0,1.003)
SOT223
  rect 1.194x2.21 smd: 1(-2.3,-3.1) 2(0,-3.1) 3(2.3,-3.1)
  rect 3.734x2.21 smd: 4(0,3.1)
SW2_SPST_4X3_SM
  rect 0.965x1.397 smd: 1(-2.075,0) 2(2.075,0)
  rect 1.143x0.762 smd: G1(-1.575,1.525) G2(-1.575,-1.525) G3(1.575,1.525) G4(1.575,-1.525)
TP_TH_063
  round 2.311 hole 1.6: 1(0,0)
TPAD_020
  round 0.508 smd: 1(0,0)
TPAD_030
  round 0.762 smd: 1(0,0)
TPAD_040
  round 1.016 smd: 1(0,0)
UDFN6_1P45X1_0P5MM
  rect 0.762x0.305 smd: 1(-0.5,0.5) 2(-0.5,0) 3(-0.5,-0.5) 4(0.5,-0.5) 5(0.5,0) 6(0.5,0.5)
UDFN6_1X1P5MM
  rect 0.584x0.305 smd: 1(-0.418,0.5)
  rect 0.508x0.305 smd: 2(-0.38,0) 3(-0.38,-0.5) 4(0.38,-0.5) 5(0.38,0) 6(0.38,0.5)
unnamed#2
  round 1.016 smd: (0,0)
XQFN8_1P45X1P25MM
  rect 0.787x0.203 smd: 1(-0.75,0)
  rect 0.203x0.711 smd: 2(-0.4,-0.65) 3(0,-0.65) 4(0.4,-0.65) 6(0.4,0.65) 7(0,0.65) 8(-0.4,0.65)
  rect 0.711x0.203 smd: 5(0.75,0)
XTAL2-3P2X1P5-SM
  rect 1.092x1.905 smd: 1(-1.25,0) 2(1.25,0)
XTAL3_3P35X1P45_SM
  rect 0.406x2.108 smd: 1(1.2,0) 2(0,0) 3(-1.2,0)
XTAL4_2P1X1P7MM_SM
  rect 0.864x0.762 smd: 1(-0.675,-0.525) 2(0.675,-0.525) 3(0.675,0.525) 4(-0.675,0.525)

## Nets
GND: ANT1.2 BT1.2(-) C1.2 C2.2 C3.2 C4.2 C5.2 C6.2 C7.2 C8.2 C9.2 C10.2 C11.2 C12.2 C13.2 C14.2 C16.2 C17.2 C18.2 C19.2 C20.2 C22.2 C23.2 C24.2 C25.2 C26.2 C27.2 C28.2 C29.2 C30.2 C31.2 C32.2 C33.2 C34.2 C35.2 C36.2 C37.2 C38.2 C39.2 C40.2 C41.2 C42.2 C43.2 C44.2 C45.2 C46.2 C47.2 C48.2 C49.2 C50.2 C51.2 C52.2 C53.2 C54.2 C56.2 C58.2 C59.2 C60.2 C61.2 C62.2 C63.1 C64.2 C65.2 C66.2 C67.2 C68.2 C69.2 C71.2 C72.2 C73.2 C74.2 C75.2 C78.2 C79.2 C80.2 C81.2 C82.2 C86.2 C87.2 D14.A D15.2(A2) D16.2(A2) J2.7 J3.6 J3.7 J11.5 J12.3 J12.5 J13.4 J14.3 J14.5 J21.2 J21.3 J21.4 J21.5(SHIELD4) J23.4 J32.2 J32.3 J32.SH1 J32.SH2(SHIELD2) J33.1 J34.2 Q1.2(SOURCE) Q2.2(SOURCE) Q3.2(SOURCE) Q4.2(SOURCE) R4.2 R15.2 R31.2 R49.2 R51.2 R57.2 R62.2 R63.2 R64.1 R75.2 R80.1 R85.2 R94.1 R98.1 R101.2 SW1.1 SW1.G1 SW1.G2 SW1.G3 SW1.G4 SW2.2(S2) SW2.G1 SW2.G2 SW2.G3 SW2.G4 SW3.2(S2) SW3.G1 SW3.G2 SW3.G3 SW3.G4 SW4.G1 SW4.G2 SW4.G3 SW4.G4 TP4.1(PIN1) TP19.1(PIN1) TP25.1(PIN1) TP39.1(PIN1) U1.4 U3.7 U3.9 U4.2 U5.2 U5.8 U5.33 U6.3 U6.4 U7.3 U7.4 U8.2 U9.2 U10.5 U11.3 U11.5 U11.12 U11.13 U12.2 U13.2 U14.2 U15.1 U16.1 U17.2 U18.11 U18.26 U18.34 U18.49 U19.2 U19.8 U20.2 U20.5 X1.2 Y1.2 Y1.4
P1V8_3V3_BRD: C13.1 C22.1 C31.1 C35.1 C49.1 C62.1 C75.1 J3.2 J3.4 J28.2 R9.1 R14.1 R17.1 R21.1 R30.1 R32.1 R36.1 R39.1 R41.1 R44.1 R46.1 R60.1 SH17.2 U3.6 U7.8(VCCB) U11.1(VDDIO) U12.6(VCCB) U17.6(VCCB) U20.6(VCCB)
P3V3_BATT: BT1.1 D10.A
P3V3_LDO: C38.1 C39.1 D8.C J35.1 U11.14
P3V3_SDA: C3.1 C8.1 C9.1 C10.1 C11.1 C20.1 C25.1 C29.1 C42.1 C43.1 J14.1 R1.2 R5.1 R8.1 R10.1 R16.1 R38.1 R42.1 R43.1 R55.1 R65.1 R66.1 SH16.1 U1.1 U4.1 U5.1 U5.7 U5.11 U6.7 U8.5 U13.1 U14.1
P5V: C24.1 C32.1 C41.1 C53.1 C54.1 C59.1 C61.1 D13.A R45.2 R50.1 R54.2 R71.1 U7.7 U12.1 U15.2(VOUT) U15.4 U17.1 U19.3 U19.5(VIO) U20.1
P5V0_SDA_USB_CONN_VBUS: D14.C J11.1(VBUS) L1.1 TP5.1(PIN1)
P5V_LDO_OUT: C71.1 D12.A J34.3
P5V_SDA: C5.1 C21.1 C27.1 L1.2 R48.1 R52.1 R56.1 TP35.1(PIN1) U5.6 U9.1
P5V_SDA_PSW: D3.A D4.A TP29.1(PIN1) U9.6(VOUT)
P5V_USB: D4.C D5.A D12.C J3.5
P12V: D11.A J13.2 J23.3 J32.1
P12V_VBAT: C33.1 C48.1 C68.1 D2.A D11.C(CATHODE) U10.7(VBAT) U15.3
VDD_1P45OUT_PMCIN: C66.1 L5.1 U18.15
VDD_BRD: C64.1 J12.1 J24.3 J27.1 J28.1 J29.1 R69.1 U18.13
VDD_MCU: C44.1 C65.1 J29.2 L4.1 U18.20 U18.44
VDD_RF: C46.1 C78.1 C86.1 C87.1 J31.2 U18.32 U18.35 U18.36
VDD_RFF: C67.1 J30.2 J31.1 L5.2
VDDA: C69.1 L4.2 U18.28
A0: J4.1 R99.2
A1: J4.2 SH13.2
A2: J4.3 SH14.2
A3: J4.4 SH15.2
A4: J4.5 R96.2
A5: J4.6 R97.2 R100.2
ADC0_DM0/CMP0_IN1: R19.1 R97.1 U18.25
ADC0_DP0/CMP0_IN0: R25.1 R99.1 U18.24
ANT: C50.1 L2.1 U18.33
BYP_FXOS8700CQ: C34.1 U11.2
CAN_HI: J23.1 R77.2 U19.7
CAN_LO: J23.2 R73.1 U19.6
CAN_RX: U17.3 U19.4
CAN_TX: U19.1 U20.3
CRST_FXOS8700CQ: C19.1 U11.8
CS: R21.2 R23.2 TP14.1(PIN1) U3.4
D0: J1.1 J8.2
D1: J1.2 J10.2
D2: J1.3 SH11.2
D3: J1.4 SH10.2
D4: J1.5 SH9.2
D5: J1.6 SH8.2
D6: J1.7 SH7.2
D7: J1.8 SH6.2
D8: J2.1 SH5.2
D9: J2.2 SH2.2
D10: J2.3 SH4.2
D11: J2.4 J9.2
D12: J2.5 J7.2
D13: J2.6 SH1.2
D14: J2.9 R7.2
D15: J2.10 R6.1
DCDC_LN: L3.2 U18.12 U18.14
DCDC_LP: L3.1 U18.10
EXTAL_32M: U18.30 Y1.3
I2C1_SCL: R44.2 R47.1 TP20.1(PIN1) U11.4
I2C1_SDA: R37.1 R41.2 TP17.1(PIN1) U11.6
INT1_COMBO_R: R61.1 U11.11
INT2_COMBO: R39.2 R40.2 TP32.1(PIN1)
INT2_COMBO_R: R40.1 U11.9
LEDRGB_BLUE: LED4.3 R93.2
LEDRGB_GREEN: LED4.4 R90.2
LEDRGB_RED: LED4.1(RED_C) R87.2
LIN: C28.1 J13.1 R27.1 R34.1 U10.6
LIN_RX_LS: R54.1 U10.1 U12.3
LIN_SLP: R45.1 U7.6 U10.2
LIN_TX_LS: U7.5 U10.4
LVLRST_EN: R1.1 U1.5
MIC2005_CSLEW: C21.2 U9.5
P5-9V_VIN: C72.1 C73.1 C74.1 D6.A J3.8 J34.1
P5-9V_VIN_VR: C40.1 D3.C D5.C D6.C D13.C TP21.1(PIN1) U16.3
P_LED: LED2.A LED3.A LED4.2 R70.1 SH12.1
POWER_EN: R53.1 U5.31
PSWITCH: J38.2 U18.8
PSWTICH_CON: C36.1 J38.1 R63.1 SW4.1
PTA0/SWD_DIO: J12.2 J16.2 TP38.1(PIN1) U18.1
PTA1/SWD_CLK: J15.1 TP36.1(PIN1) U18.2
PTA16: R82.2 SH5.1 U18.4
PTA17: R58.2 SH9.1 U18.5
PTA18: R28.2 SH7.1 U18.6
PTA19: R60.2 R61.2 SH4.1 U18.7
PTB0: R6.2 R47.2 R100.1 U18.16
PTB1: R7.1 R37.2 R96.1 U18.17
PTB2: R89.2 SH14.1 U18.18
PTB3: R92.1 SH15.1 U18.19
PTB16/XTAL_32K: U18.21 Y2.1
PTB17/EXTAL_32K: U18.22 Y2.2
PTB18: C7.1 R9.2 SH13.1 SW2.1 TP6.1(PIN1) U18.23
PTC1: C79.1 R76.1 SH2.1 U18.37
PTC2: C23.1 C80.1 R36.2 SW3.1 TP18.1(PIN1) U18.38
PTC3: C81.1 R81.2 SH10.1 U18.39
PTC4: C82.1 R74.2 SH8.1 U18.40
PTC5: R35.2 SH6.1 U18.41
PTC16: R13.1 SH1.1 U18.45
PTC17: J9.1 R11.1 U18.46
PTC18: J7.1 R12.2 U18.47
PTC19: R23.1 SH11.1 U18.48
RF_50: C51.1 C55.1 C57.1 L2.2
RF_ANT: ANT1.1(SIGNAL) R72.2
RF_SMA: C57.2 J21.1
RST_FXOS8700CQ: R64.2 R67.1 U11.16
RST_TGTMCU_B: C47.1 J3.3 J5.3 J12.10(B5) R2.2 R3.2 R67.2 R69.2 TP3.1(PIN1) U1.7 U18.3
SA0_FXOS8700CQ: R31.1 R32.2 U11.7
SA1_FXOS8700CQ: R46.2 R51.1 U11.10
SCK: R13.2 R14.2 TP11.1(PIN1) U3.2
SDA_EXTAL: C18.1 U5.17 X1.3
SDA_JTAG_TCLK: J14.4 U5.12
SDA_JTAG_TDI: J14.8 U5.13
SDA_JTAG_TDO: J14.6 U5.14
SDA_JTAG_TMS: J14.2 R66.2 U5.15
SDA_LED: D1.C(CATHODE) TP8.1(PIN1) U5.29
SDA_LED_R: D1.A R10.2
SDA_RST: J14.10(B5) R48.2 R49.1 TP34.1(PIN1) U5.19
SDA_RST_LED: LED1.A R8.2
SDA_RST_TGTMCU_B: J6.2 U5.21
SDA_RST_TGTMCU_J_B: J5.1 J6.1 LED1.C(CATHODE) R3.1 R5.2 U1.2
SDA_RX_EN: R16.2 U4.5
SDA_SPI0_SCK: TP37.1(PIN1) U5.26 U14.3
SDA_SPI0_SIN: TP28.1(PIN1) U5.28 U6.5
SDA_SPI0_SOUT: TP33.1(PIN1) U5.27 U13.3
SDA_SWD_EN: R65.2 U8.6 U14.5
SDA_SWD_EN_B: R43.2 U5.16 U8.1
SDA_SWD_OE: R55.2 U8.4(Y\2\) U13.5
SDA_SWD_OE_B: R42.2 U5.20 U8.3
SDA_USB_CONN_DN: D16.1 J11.2 R22.1 TP12.1(PIN1)
SDA_USB_CONN_DP: D15.1 J11.3 R18.1 TP7.1(PIN1)
SDA_USB_DN: R22.2 U5.4
SDA_USB_DP: R18.2 U5.3
SDA_USB_P5V_SENSE: R56.2 R62.1 TP24.1(PIN1) U5.30
SDA_VOUT33: C6.1 SH16.2 U5.5
SDA_XTAL: C16.1 U5.18 X1.1
SI: R11.2 TP9.1(PIN1) U3.1
SO: R12.1 TP10.1(PIN1) U3.8
SW1_RST_B: C4.1 J5.2 SW1.2(S2)
SWD_CLK_TGTMCU: J12.4 J15.2 J17.2 TP22.1(PIN1)
SWD_CLK_TGTMCU_BUF: J17.1 U14.4
SWD_DIO_TGTMCU_BUF: J16.1 U6.2 U13.4
TC_EXTAL_TP: TP31.1(PIN1) U5.10
TC_XTAL_TP: TP30.1(PIN1) U5.9(XTAL32)
THER_A: C15.1 R24.1 R30.2 RT1.1
THER_B: C15.2 R15.1 R20.1 RT1.2
TP_2102_A: TP2.1(PIN1) U1.3
TP_2102_B: TP1.1(PIN1) U1.6
UART0_RX_TGTMCU: J8.1 R26.2 U18.42
UART0_TX_TGTMCU: J10.1 R29.2 U18.43
UART1_CTS_TGTMCU_R: U5.23
UART1_RTS_TGTMCU_R: U5.22
UART1_RX_TGTMCU_BUF: R26.1 TP15.1(PIN1) U4.4
UART1_RX_TGTMCU_R: TP27.1(PIN1) U4.3 U5.25
UART1_TX_TGTMCU_BUF: R29.1 R33.2 TP16.1(PIN1) U6.1
UART1_TX_TGTMCU_R: TP26.1(PIN1) U5.24 U6.6
V_BATT: C56.1 D10.C J35.3 R70.2
V_LDO_OUT: C45.1 D8.A U16.2(VOUT) U16.4
V_MAIN: C58.1 J24.1 J27.2 J30.1 J35.2 J38.3 SW4.2(S2) U18.9
V_TGTMCU: C1.1 C12.1 C26.1 C30.1 C37.1 R2.1 R33.1 SH17.1 U1.8(VCCB) U4.6(VCCB) U6.8(VCCB) U13.6(VCCB) U14.6(VCCB)
VREFH: J2.8 SH3.2
VREFH/VREF_OUT: C60.1 SH3.1 U18.27
VTRG_EN: R52.2 R53.2 R57.1 U9.3
VTRG_FAULT_B: R38.2 TP23.1(PIN1) U5.32 U9.4
WP/RST: R17.2 U3.3 U3.5(W\P\)
XTAL_32M: U18.31 Y1.1
XTAL_OUT: C70.2 U18.29(XTAL_OUT)
XTAL_OUT_CON: C70.1 J33.2
N21167890: C2.1 J11.6 J11.7 J11.8 J11.9 R4.1
N21328439: C17.1 R24.2 R25.2
N21328458: C14.1 R19.2 R20.2
N21328514: Q4.3 R88.1
N21337706: D2.C R27.2 R34.2
N21361580: C63.2 R73.2 R77.1
N21445715: J11.4 TP13.1(PIN1)
N21455862: Q1.1 R76.2 R80.2
N21456098: Q1.3 R87.1
N21456788: Q2.1 R82.1 R85.1
N21456802: Q2.3 R90.1
N21456812: Q3.1 R89.1 R94.2
N21456830: Q3.3 R93.1
N21501528: Q4.1 R92.2 R98.2
N21519740: J24.2 SH12.2
N21560793: R35.1 U7.1
N21560827: J39.1 R50.2
N21560833: R58.1 U12.4
N21560903: R28.1 U7.2
N21561545: R71.2 U17.5
N21561559: R74.1 U17.4
N21611491: R81.1 U20.4
N21837447: C52.1 C55.2 R72.1
N21928909: J39.2 U12.5
N21929178: J39.3 R101.1
N213293921: LED3.C(CATHODE) R88.2
N215011841: LED2.C(CATHODE) R75.1

Pads without a net: J3 1; J12 6 7 8 9; J13 3; J14 7 9; U10 3 8; U11 15

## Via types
v1: diameter 0.508, hole 0.254, TOP to BOTTOM, 758 vias
v2: diameter 0.356, hole 0.203, TOP to BOTTOM, 26 vias
v3: diameter 0.457, hole 0.203, TOP to BOTTOM, 696 vias

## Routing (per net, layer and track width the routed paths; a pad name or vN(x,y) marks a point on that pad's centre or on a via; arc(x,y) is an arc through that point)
GND: length 288.9
  TOP w0.254: C48.2 11.95,19.86 v1(12.2,19.61) ; v3(88.28,11.94) 87.82,11.94 C65.2 ; C3.2 v1(14.31,48.56) ; v1(16.19,18.87) 16.68,18.87 C54.2 17.08,18.47 U17.2 ; U1.4 14.28,50.01 14.62,50.34 v1(14.62,50.47) ; v1(46.42,31.22) 46.8,31.6 U8.2 ; C18.2 47.44,36.4 v1(47.02,36.82) 47.55,37.36 C16.2
  TOP w0.279: X1.2 48.47,36.82 ; U11.5 71.68,31.1 ; U11.13 67.52,29.1 ; U11.3 72.05,30.1 ; U5.2 41.69,39.71 v1(42.94,38.46) 41.19,36.7 U5.8 40.26,36.42 ; U11.12 67.38,29.6
  TOP w0.305: 52.18,24.05 U14.2 ; U6.3 54,37.1 ; U6.4 53.4,37.26 ; U13.2 52.41,29.34 ; U5.2 v1(39.66,39.71)
  TOP w0.381: TP19.1 95.03,40.59 ; TP19.1 95.03,37.9 ; TP19.1 93.69,39.24 ; TP19.1 96.38,39.24 ; J32.3 17.95,12.51 ; J32.3 17.03,10.59 ; J32.3 18.86,10.59 ; J32.3 17.95,8.67 ; C62.2 20.33,15.04 19.82,15.54 U20.5 ; J32.SH1 11.85,5.35 ; J32.SH1 10.93,3.29 ; J32.SH1 11.85,1.23 ; J32.SH1 12.76,3.29 ; J32.SH2 22.66,3.29 ; J32.SH2 20.83,3.29 ; J32.SH2 21.75,1.23 ; J32.SH2 21.75,5.35 ; J12.5 60.6,32.92 ; U12.2 17.28,29.77 C32.2 ; 65.65,2.59 65.65,3.63 ; 65.65,2.59 65.65,1.55 ; 65.65,2.59 66.69,2.59 ; 65.65,2.59 64.6,2.59 ; 63.11,1.55 63.11,2.59 ; 63.11,2.59 64.15,2.59 ; 63.11,2.59 62.06,2.59 ; 63.11,2.59 63.11,3.63 ; J32.2 13.66,10.59 ; J32.2 12.75,8.67 ; J32.2 11.83,10.59 ; J32.2 12.75,12.51 ; U20.2 18.17,15.54 17.67,15.04 C61.2 17.28,15.04 v1(16.78,14.53) ; U4.2 52.08,39.4 v1(51.96,39.52) ; J33.1 105,3.78 ; J33.1 104.05,2.83 ; J33.1 103.1,3.78 ; J33.1 104.05,4.74 ; J13.4 2.04,25.45 ; J13.4 2.04,23.42 ; J13.4 1.03,24.43 ; J13.4 3.06,24.43 ; 2.04,7.67 J23.4 ; J23.4 1.03,8.69 ; J23.4 2.04,9.7 ; J23.4 3.06,8.69 ; 48.98,49.8 J2.7 ; J2.7 47.97,50.81 ; J2.7 50,50.81 ; J2.7 48.98,51.83 ; J12.3 60.6,31.65 ; J14.3 47.65,24.94 ; 28.52,3.48 J34.2 ; J34.2 29.48,2.53 ; J34.2 29.48,4.43 ; J14.5 47.65,26.21
  TOP w0.457: J11.5 5.73,40.79
  TOP w0.508: C22.2 v1(19.82,33.45) ; v1(58.64,16.23) R63.2 C36.2 ; C43.2 49.29,25.2 v1(49.54,25.45) ; C27.2 v1(34.96,31.85) ; v1(34.96,31.85) U9.2 36.92,31.85 v1(37.35,31.42) ; v1(34.96,31.85) v1(34.96,30.91) ; v1(18.94,19.74) 19.32,20.12 C49.2 ; C47.2 81.47,22.78 v1(81.95,22.3) ; C32.2 v1(16.4,29.9) ; C24.2 v1(16.27,32.44) ; C63.1 v1(7.12,12.62) ; v1(6.16,28.5) 6.49,28.83 6.49,29.26 ; C9.2 37,42.88 v1(37.22,43.1) ; 16.14,15.8 C59.2 16.4,15.42 v1(16.14,15.16) ; C75.2 v1(53.96,7.06) ; C53.2 v1(5.98,19.23) ; C31.2 v1(19.19,31.29)
  TOP w1.016: C68.2 v1(6.74,8.69)
  GND w0.381: J32.SH1 11.85,5.35 ; J32.SH1 11.85,1.23 ; J32.SH1 12.76,3.29 ; J32.SH1 10.93,3.29 ; J2.7 48.98,51.83 ; J2.7 50,50.81 ; J2.7 48.98,49.8 ; J2.7 47.97,50.81 ; J33.1 104.05,4.74 ; J33.1 105,3.78 ; J33.1 104.05,2.83 ; J33.1 103.1,3.78 ; 20.83,3.29 J32.SH2 ; J32.SH2 22.66,3.29 ; J32.SH2 21.75,1.23 ; J32.SH2 21.75,5.35 ; 2.04,7.67 J23.4 ; J23.4 2.04,9.7 ; J23.4 1.03,8.69 ; J23.4 3.06,8.69 ; TP19.1 95.03,40.59 ; TP19.1 95.03,37.9 ; TP19.1 96.38,39.24 ; TP19.1 93.69,39.24 ; J13.4 3.06,24.43 ; J13.4 1.03,24.43 ; J13.4 2.04,23.42 ; J13.4 2.04,25.45 ; 62.06,2.59 63.11,2.59 ; 63.11,2.59 64.15,2.59 ; 63.11,2.59 63.11,1.55 ; 63.11,2.59 63.11,3.63 ; J34.2 29.48,4.43 ; J34.2 28.52,3.48 ; J34.2 30.43,3.48 ; J34.2 29.48,2.53 ; 65.65,2.59 66.69,2.59 ; 65.65,2.59 65.65,1.55 ; 65.65,2.59 64.6,2.59 ; 65.65,2.59 65.65,3.63 ; J14.3 47.65,24.94 ; J12.3 60.6,31.65 ; J14.5 47.65,26.21 ; J12.5 60.6,32.92 ; J32.2 13.66,10.59 ; J32.2 11.83,10.59 ; J32.2 12.75,12.51 ; J32.2 12.75,8.67 ; J32.3 18.86,10.59 ; J32.3 17.95,8.67 ; J32.3 17.95,12.51 ; J32.3 17.03,10.59
  INT_1 w0.381: 28.52,3.48 J34.2 ; J34.2 29.48,4.43 ; J34.2 30.43,3.48 ; J34.2 29.48,2.53 ; 11.85,1.23 J32.SH1 ; J32.SH1 11.85,5.35 ; J32.SH1 12.76,3.29 ; J32.SH1 10.93,3.29 ; 104.05,2.83 J33.1 ; J33.1 104.05,4.74 ; J33.1 105,3.78 ; J33.1 103.1,3.78 ; J32.SH2 21.75,5.35 ; J32.SH2 21.75,1.23 ; J32.SH2 20.83,3.29 ; J32.SH2 22.66,3.29 ; TP19.1 95.03,40.59 ; TP19.1 93.69,39.24 ; TP19.1 96.38,39.24 ; TP19.1 95.03,37.9 ; 64.6,2.59 65.65,2.59 ; 65.65,2.59 65.65,3.63 ; 65.65,2.59 66.69,2.59 ; 2.04,7.67 J23.4 ; J23.4 2.04,9.7 ; J23.4 3.06,8.69 ; J23.4 1.03,8.69 ; 48.98,49.8 J2.7 ; J2.7 48.98,51.83 ; J2.7 50,50.81 ; J2.7 47.97,50.81 ; J14.3 47.65,24.94 ; 17.95,8.67 J32.3 ; J32.3 17.95,12.51 ; J32.3 17.03,10.59 ; J32.3 18.86,10.59 ; 11.83,10.59 J32.2 ; J32.2 13.66,10.59 ; J32.2 12.75,12.51 ; J32.2 12.75,8.67 ; 1.03,24.43 J13.4 ; J13.4 2.04,23.42 ; J13.4 2.04,25.45 ; 63.11,2.59 63.11,3.63 ; 63.11,2.59 64.15,2.59 ; 63.11,2.59 62.06,2.59 ; J12.5 60.6,32.92 ; J14.5 47.65,26.21 ; J12.3 60.6,31.65
  BOTTOM w0.381: J2.7 48.98,51.83 ; J2.7 48.98,49.8 ; J2.7 47.97,50.81 ; J2.7 50,50.81 ; 1.03,8.69 J23.4 ; J23.4 2.04,7.67 ; J23.4 2.04,9.7 ; J23.4 3.06,8.69 ; J14.5 47.65,26.21 ; 20.83,3.29 J32.SH2 ; J32.SH2 22.66,3.29 ; J32.SH2 21.75,5.35 ; J32.SH2 21.75,1.23 ; 95.03,37.9 TP19.1 ; TP19.1 96.38,39.24 ; TP19.1 93.69,39.24 ; TP19.1 95.03,40.59 ; 62.06,2.59 63.11,2.59 ; 63.11,2.59 64.15,2.59 ; 63.11,2.59 63.11,1.55 ; 63.11,2.59 63.11,3.63 ; J12.5 60.6,32.92 ; 1.03,24.43 J13.4 ; J13.4 2.04,25.45 ; J13.4 2.04,23.42 ; 65.65,2.59 66.69,2.59 ; 65.65,2.59 65.65,1.55 ; 65.65,2.59 65.65,3.63 ; 65.65,2.59 64.6,2.59 ; J32.SH1 12.76,3.29 ; J32.SH1 11.85,5.35 ; J32.SH1 11.85,1.23 ; J32.SH1 10.93,3.29 ; J32.2 12.75,12.51 ; J32.2 12.75,8.67 ; J32.2 13.66,10.59 ; J32.2 11.83,10.59 ; J33.1 105,3.78 ; J33.1 104.05,4.74 ; J33.1 103.1,3.78 ; J33.1 104.05,2.83 ; 29.48,2.53 J34.2 ; J34.2 30.43,3.48 ; J34.2 28.52,3.48 ; J34.2 29.48,4.43 ; 17.95,8.67 J32.3 ; J32.3 17.03,10.59 ; J32.3 18.86,10.59 ; J32.3 17.95,12.51 ; J14.3 47.65,24.94 ; J12.3 60.6,31.65
  BOTTOM w0.508: 30.01,36.7 BT1.2 30.01,33.57 v1(27.56,36.02)
  vias: v1(1.54,35.23) v1(1.54,22.53) v1(1.54,21.26) v1(1.54,19.99) v1(1.54,18.72) v1(1.54,6.02) v1(2.81,36.5) v1(2.81,4.75) v1(3.57,47.04) v1(3.95,48.69) v1(4.08,33.45) v1(4.08,32.44) v1(4.08,6.02) v1(4.33,30.4) v1(4.84,47.7) v1(4.94,52.48) v1(4.97,32.31) v1(4.97,12.37) v1(4.97,8.18) v1(5.09,33.45) v1(5.22,6.91) v1(5.35,30.4) v1(5.35,29.26) v1(5.35,11.35) v1(5.35,4.75) v1(5.98,12.37) v1(6.49,39.67) v1(6.49,38.28) v1(6.49,21.51) v1(6.62,6.02) v1(6.62,3.48) v1(6.62,0.94) v1(7.12,48.06) v1(7.25,46.66) v1(7.89,38.4) v1(7.89,14.4) v1(7.89,7.54) v1(7.89,2.21) v1(7.96,47.57) v1(8.01,33.83) v1(8.01,13.51) v1(8.62,52.48) v1(8.78,39.29) v1(9.03,43.1) v1(9.16,46.53) v1(9.16,34.21) v1(9.16,6.02) v1(9.16,3.48) v1(9.16,0.94) v1(9.92,39.8) v1(10.43,4.75) v1(10.43,2.21) v1(10.5,50.09) v1(10.81,38.79) v1(10.93,15.29) v1(11.06,43.23) v1(11.19,40.56) v1(11.7,52.5) v1(11.95,27.48) v1(11.95,26.34) v1(11.95,25.07) v1(12.84,43.1) v1(13.6,41.2) v1(13.73,27.61) v1(13.86,13.26) v1(14.24,44.75) v1(15.13,44.75) v1(15.13,12.12) v1(15.51,27.74) v1(15.63,41.2) v1(15.76,37.13) v1(15.79,36.07) v1(15.76,24.82) v1(15.89,13.26) v1(16.01,38.2) v1(16.14,22.53) v1(16.9,41.2) v1(17.03,43.23) v1(17.03,38.58) v1(17.03,27.86) v1(18.05,43.18) v1(18.17,24.82) v1(18.17,13.26) v1(18.3,22.53) v1(18.55,38.58) v1(18.5,36.35) v1(18.55,27.61) v1(19.32,45.14) v1(19.34,43.21) v1(19.39,35.79) v1(20.1,41.25) v1(20.1,38.58) v1(20.94,43.13) v1(21.07,14.53) v1(21.22,48.56) v1(21.5,41.25) v1(21.68,45.01) v1(21.6,7.16) v1(21.98,5.89) v1(22.95,45.19) v1(23.15,10.87) v1(23.28,17.42) v1(23.33,15.24) v1(23.46,43) v1(23.43,9.75) v1(23.69,41.25) v1(23.69,38.58) v1(23.61,20.7) v1(24.14,4.02) v1(24.4,0.94) v1(24.73,32.94) v1(24.83,13.77) v1(24.9,49.33) v1(25.23,41.25) v1(25.23,38.58) v1(25.29,29.13) v1(26.05,12.75) v1(26.17,47.55) v1(26.26,1.45) v1(26.56,52.5) v1(26.68,27.3) v1(26.78,41.25) v1(26.78,38.58) v1(27.17,13.82) v1(27.55,42.93) v1(27.7,47.17) v1(27.8,9.47) v1(27.8,8.43) v1(27.88,0.97) v1(28.21,27.48) v1(28.31,41.25) v1(28.33,38.58) v1(28.56,10.24) v1(28.5,2.21) v1(28.97,43.61) v1(29.1,36.25) v1(29.35,49.2) v1(29.32,9.47) v1(29.32,8.43) v1(29.32,1.23) v1(29.86,41.25) v1(29.88,38.58) v1(29.98,2.23) v1(30.09,43.64) v1(30.09,10.24) v1(30.19,17.68) v1(30.37,28.83) v1(30.37,23.16) v1(30.44,0.71) v1(30.87,9.45) v1(30.87,8.43) v1(31.25,47.17) v1(31.2,18.97) v1(31.23,17.88) v1(31.33,31.7) v1(31.38,30.07) v1(31.41,41.25) v1(31.43,27.81) v1(31.58,16.89) v1(31.53,1.35) v1(31.64,37.82) v1(31.89,15.85) v1(32.02,33.02) v1(31.99,26.24) v1(32.14,9.45) v1(32.14,8.43) v1(32.27,49.83) v1(32.41,0.7) v1(32.55,18.01) v1(33.03,27.79) v1(33.19,37.87) v1(33.16,36.09) v1(33.16,9.45) v1(33.38,1.23) v1(33.46,41.25) v1(33.41,23.16) v1(33.49,28.88) v1(33.55,24.88) v1(33.67,8.43) v1(33.69,26.29) v1(33.87,19.3) v1(33.82,18.11) v1(34.18,52.76) v1(34.63,27.74) v1(34.81,24.94) v1(35.06,20.4) v1(35.06,17.07) v1(35.09,19.23) v1(35.09,18.08) v1(35.27,26.34) v1(35.45,43.1) v1(35.55,23.64) v1(35.95,36.75) v1(36.44,25.02) v1(36.51,26.37) v1(36.72,27.3) v1(36.73,21.23) v1(37.2,23.83) v1(37.81,27.76) v1(37.88,26.44) v1(38.49,52.63) v1(38.54,23.52) v1(38.62,25.2) v1(38.75,28.12) v1(38.87,36.07) v1(39.13,47.78) v1(39.2,26.29) v1(39.43,43.28) v1(39.54,27.23) v1(39.56,20.75) v1(39.64,24.94) v1(40.02,27.99) v1(40.04,23.67) v1(40.65,49.07) v1(40.65,36.02) v1(40.75,25.5) v1(40.93,4.6) v1(41.03,43.23) v1(41.16,32.44) v1(41.11,29.69) v1(41.14,28.37) v1(41.16,23.55) v1(41.16,20.78) v1(42.08,52.28) v1(42.05,43.48) v1(42.18,34.21) v1(42.18,23.55) v1(42.51,49.83) v1(42.51,31.34) v1(42.53,20.68) v1(42.71,27.15) v1(42.81,37.26) v1(42.91,39.42) v1(43.09,4.17) v1(43.47,25.76) v1(43.64,26.81) v1(43.73,20.78) v1(44.11,52.28) v1(44.18,39.47) v1(44.21,38.53) v1(44.21,37.26) v1(44.23,2.95) v1(45.07,20.68) v1(45.33,49.89) v1(45.33,1.73) v1(45.48,35.97) v1(46.14,52.28) v1(46.32,1.02) v1(46.55,35.81) v1(46.6,48.06) v1(46.6,19.13) v1(47.76,29.44) v1(47.74,28.09) v1(47.8,26.9) v1(47.84,25.53) v1(48.02,49.81) v1(48.07,22.66) v1(48.18,52.28) v1(48.4,38.86) v1(48.4,4.24) v1(48.6,47.19) v1(48.7,22) v1(49.54,30.15) v1(49.54,29.21) v1(49.52,27.76) v1(49.54,26.7) v1(49.75,20.8) v1(50.21,52.28) v1(50.33,49.86) v1(50.3,16.05) v1(51.04,46.53) v1(51.42,45.11) v1(51.52,20.02) v1(51.7,47.35) v1(51.73,43.84) v1(51.73,6.22) v1(51.83,29.82) v1(52.08,23.29) v1(52.01,21.97) v1(52.24,52.28) v1(52.34,18.59) v1(53.1,40.67) v1(53.35,38.02) v1(54.27,52.28) v1(54.37,19.48) v1(54.65,36.93) v1(55.38,49.83) v1(55.64,25.83) v1(55.77,41.58) v1(55.79,5.56) v1(56.3,52.28) v1(56.76,28.83) v1(56.76,22.15) v1(56.88,29.74) v1(57.11,19.76) v1(57.37,43.81) v1(57.44,33.5) v1(57.42,31.67) v1(57.42,28.17) v1(57.4,24.3) v1(57.49,32.61) v1(57.77,38.43) v1(57.82,49.86) v1(57.82,40.13) v1(57.92,41.71) v1(58.05,47.29) v1(58.33,52.28) v1(58.36,45.97) v1(58.86,27.08) v1(59.65,39.45) v1(60.11,26.82) v1(60.27,43.5) v1(60.36,52.28) v1(60.3,37.84) v1(60.39,49.83) v1(60.46,47.29) v1(60.97,45.09) v1(61.44,37.91) v1(61.49,43.53) v1(62.4,52.28) v1(62.41,35.98) v1(62.42,23.39) v1(62.6,20.4) v1(62.73,24.74) v1(62.75,22.25) v1(62.9,49.91) v1(63,47.29) v1(63.26,17.7) v1(63.39,28.88) v1(64.35,45.16) v1(64.43,52.28) v1(64.55,6.93) v1(64.68,38) v1(64.78,24.94) v1(64.91,22.78) v1(65.54,47.29) v1(65.49,45.26) v1(66.28,49.81) v1(66.46,52.28) v1(66.46,51) v1(66.66,46.2) v1(67.07,47.29) v1(67.09,7.29) v1(67.32,23.55) v1(67.45,20.7) v1(67.42,14.38) v1(67.58,41.88) v1(67.58,39.67) v1(67.75,12.9) v1(67.93,38.05) v1(68.06,9.53) v1(68.41,45.03) v1(68.47,23.55) v1(68.49,52.28) v1(68.8,20.78) v1(69.05,0.69) v1(69.1,12.9) v1(69.48,49.83) v1(69.61,46.91) v1(69.61,23.55) v1(69.71,41.88) v1(69.74,39.67) v1(70.32,12.9) v1(70.52,52.28) v1(70.68,3.33) v1(70.68,2.11) v1(70.62,0.63) v1(70.88,9.19) v1(70.95,14.05) v1(71.11,6.93) v1(71.74,46.46) v1(71.79,48.26) v1(72,12.9) v1(72.33,24.84) v1(72.56,52.28) v1(72.56,45.75) v1(72.68,14) v1(72.83,47.83) v1(73.49,46.81) v1(73.6,33.15) v1(73.62,32.26) v1(73.6,31.32) v1(73.67,30.02) v1(73.8,12.42) v1(73.95,16.97) v1(73.98,7.49) v1(74.05,17.98) v1(74.08,15.42) v1(74,10.92) v1(74.59,52.28) v1(74.79,45.06) v1(75.07,49.17) v1(75.32,3.73) v1(76.09,44.5) v1(76.16,18.75) v1(76.14,17.2) v1(76.16,14.38) v1(76.21,23.55) v1(76.21,10.82) v1(76.62,52.28) v1(76.82,48.74) v1(77.18,5.16) v1(77.18,3.63) v1(77.76,14.12) v1(77.84,25.86) v1(77.86,23.67) v1(77.81,11.48) v1(77.99,48.03) v1(78.04,18.01) v1(78.02,17.09) v1(78.24,45.64) v1(78.47,10.87) v1(78.5,47.04) v1(78.55,24.41) v1(78.65,52.28) v1(78.75,49.07) v1(79.01,25.86) v1(79.31,14.53) v1(79.39,44.73) v1(79.62,24.38) v1(79.95,36.88) v1(80.1,35.92) v1(80.28,44.09) v1(80.33,48.79) v1(80.68,52.28) v1(80.63,24.33) v1(80.77,41.09) v1(80.84,12.75) v1(81.47,13.64) v1(81.57,11.96) v1(81.72,26.82) v1(81.75,24.38) v1(81.88,46.81) v1(81.9,3.56) v1(82.21,49.17) v1(82.31,1.09) v1(82.59,25.93) v1(82.71,52.28) v1(82.92,41.78) v1(82.94,14.17) v1(82.99,36.07) v1(83.35,32.61) v1(83.68,31.06) v1(84.47,41.71) v1(84.59,20.37) v1(84.59,19.35) v1(84.59,18.34) v1(84.59,17.32) v1(84.59,16.31) v1(84.59,15.29) v1(84.75,52.28) v1(84.77,8.28) v1(84.72,3.51) v1(84.85,1.09) v1(85.53,40.97) v1(85.74,20.37) v1(85.74,19.35) v1(85.74,18.34) v1(85.74,17.32) v1(85.74,16.31) v1(85.74,15.29) v1(85.84,32.18) v1(86.88,20.37) v1(86.88,19.35) v1(86.88,18.34) v1(86.88,17.32) v1(86.88,16.31) v1(86.88,15.29) v1(87.45,1.39) v1(87.64,6.71) v1(87.64,2.84) v1(87.77,42.95) v1(88.02,20.37) v1(88.02,19.35) v1(88.02,18.34) v1(88.02,17.32) v1(88.02,16.31) v1(88.02,15.29) v1(88.23,7.98) v1(88.35,4.9) v1(89.17,20.37) v1(89.17,19.35) v1(89.17,18.34) v1(89.17,17.32) v1(89.17,16.31) v1(89.17,15.29) v1(89.12,7.26) v1(89.55,39.42) v1(89.6,8.03) v1(89.78,28.6) v1(89.83,29.67) v1(90.64,31.6) v1(90.77,8) v1(91.35,14.99) v1(92.11,30.48) v1(92.09,11.02) v1(92.98,35.89) v1(93.1,6.15) v1(94.32,0.84) v1(94.65,10.06) v1(95.82,37.34) v1(96.79,30.15) v1(96.79,27.61) v1(98.06,40.31) v1(98.06,37.77) v1(98.06,31.42) v1(98.06,30.15) v1(98.06,28.88) v1(98.06,27.61) v1(98.06,26.34) v1(98.06,25.07) v1(98.41,0.58) v1(99.4,1.85) v1(99.66,0.56) v1(99.89,32.59) v1(99.94,29.85) v1(99.96,27.41) v1(99.96,25.1) v1(100.06,34.82) v1(101.03,0.56) v1(104.58,0.56) v1(105.78,0.56) v1(106.95,0.56) v1(107.84,0.56) v2(35.95,12.62) v2(86.73,23.83) v2(86.73,22.99) v2(87.57,24.43) v2(88.33,24.43) v2(89.09,24.41) v2(89.32,25.81) v2(90.08,24.43) v2(90.64,21.89) v2(90.89,24.43) v3(0.9,25.7) v3(1.03,9.83) v3(2.68,25.7) v3(3.95,45.52) v3(4.2,38.53) v3(7,30.91) v3(9.03,40.94) v3(11.95,29.64) v3(11.95,22.78) v3(12.33,32.18) v3(13.6,16.31) v3(14.74,19.1) v3(15.89,46.02) v3(16.9,50.98) v3(17.28,49.07) v3(17.54,47.29) v3(19.82,51.1) v3(20.71,18.21) v3(20.84,30.02) v3(21.09,32.44) v3(21.98,51.1) v3(22.62,7.92) v3(23.89,8.56) v3(25.29,43.99) v3(25.92,49.83) v3(26.43,33.32) v3(26.43,29.77) v3(27.44,49.83) v3(29.35,47.04) v3(32.14,42.98) v3(34.05,47.04) v3(34.94,7.8) v3(38.75,10.08) v3(40.4,0.69) v3(41.41,45.77) v3(42.68,18.34) v3(43.07,28.5) v3(43.07,1.07) v3(43.57,9.83) v3(43.7,7.92) v3(43.95,18.72) v3(44.84,45.52) v3(45.22,6.27) v3(46.49,17.07) v3(46.49,13.13) v3(46.75,43.74) v3(46.75,9.07) v3(47.64,45.39) v3(48.27,40.82) v3(48.27,32.56) v3(48.4,12.12) v3(49.03,17.83) v3(49.8,6.4) v3(50.05,11.86) v3(50.05,10.08) v3(50.43,7.92) v3(50.94,26.72) v3(51.19,36.25) v3(51.7,3.23) v3(51.83,1.83) v3(51.96,7.42) v3(52.34,27.48) v3(52.46,16.05) v3(53.35,25.96) v3(53.48,21.89) v3(53.73,16.05) v3(54.75,47.29) v3(54.75,22.78) v3(55.89,24.05) v3(55.89,16.18) v3(58.81,14.15) v3(59.63,41) v3(60.59,15.16) v3(61.23,33.58) v3(61.48,42.34) v3(63.26,30.28) v3(63.51,34.72) v3(64.02,16.05) v3(64.4,27.13) v3(64.91,26.44) v3(65.04,35.99) v3(65.67,34.72) v3(65.67,33.32) v3(65.67,29.77) v3(65.67,27.23) v3(66.56,9.58) v3(66.97,35.1) v3(67.07,34.09) v3(67.45,18.21) v3(68.11,35.84) v3(68.21,34.72) v3(70.37,20.88) v3(70.47,38.02) v3(70.88,5.13) v3(71.01,24.82) v3(72.63,41.4) v3(73.6,35.92) v3(73.67,3.73) v3(73.88,34.8) v3(74.08,40.46) v3(74.05,37.9) v3(74.1,41.43) v3(74.31,24.94) v3(74.69,26.85) v3(75.58,0.56) v3(76.34,9.45) v3(76.75,29.06) v3(76.85,40.06) v3(76.85,37.13) v3(76.85,35.1) v3(77.05,30.05) v3(77.1,41.83) v3(77.1,31.8) v3(78.57,28.7) v3(78.63,32.18) v3(78.75,30.07) v3(78.88,22.53) v3(80.33,25.88) v3(80.66,30.28) v3(80.66,11.61) v3(80.71,26.8) v3(81.47,5.18) v3(81.67,25.86) v3(81.75,44.81) v3(82.21,31.04) v3(82.26,29.26) v3(82.31,7.32) v3(82.77,47.8) v3(82.69,24.38) v3(83.58,29.9) v3(84.01,48.34) v3(84.09,11.99) v3(84.7,49.3) v3(84.8,47.27) v3(84.85,32.69) v3(84.8,10.31) v3(84.95,23.67) v3(85.05,25.68) v3(85.18,26.87) v3(85.1,11.1) v3(85.46,24.36) v3(85.71,36.4) v3(85.97,40.18) v3(86.25,47.32) v3(86.25,42.21) v3(86.22,8.84) v3(86.37,27.13) v3(86.63,48.18) v3(86.83,9.65) v3(86.88,6.02) v3(86.91,31.22) v3(87.13,28.63) v3(87.39,36.12) v3(87.57,52.35) v3(87.69,30.4) v3(88.07,32.28) v3(88.4,46.61) v3(88.4,45.09) v3(88.73,31.6) v3(88.91,52.76) v3(88.94,36.91) v3(89.01,35.74) v3(88.99,8.76) v3(89.27,42.37) v3(89.22,40.31) v3(89.34,10.46) v3(89.75,46.18) v3(89.85,41.5) v3(89.8,27.56) v3(89.8,11.73) v3(89.9,8.86) v3(90.23,7.09) v3(90.34,40.64) v3(90.69,43.48) v3(90.72,38.71) v3(90.77,37.36) v3(90.69,34.21) v3(90.82,45.39) v3(90.82,36.22) v3(90.84,29.08) v3(91,8.92) v3(91.12,32.72) v3(91.45,46.15) v3(91.4,28.12) v3(91.45,26.97) v3(91.71,29.46) v3(91.88,26.06) v3(92.01,8.89) v3(92.14,9.78) v3(92.09,6.78) v3(92.24,41.38) v3(92.24,12.04) v3(92.34,34.34) v3(92.32,25.25) v3(92.47,45.01) v3(92.42,32.16) v3(92.49,43.66) v3(92.64,29.47) v3(92.64,28.38) v3(92.62,27.24) v3(92.75,17.55) v3(92.82,37.67) v3(92.85,21.31) v3(92.98,40.31) v3(93,42.27) v3(93.26,38.84) v3(93.26,20.55) v3(93.36,24.28) v3(93.36,7.29) v3(93.41,45.95) v3(93.46,25.45) v3(93.51,23.22) v3(93.51,22.15) v3(93.66,29.47) v3(93.66,28.38) v3(93.64,27.24) v3(93.61,5.26) v3(93.87,31.34) v3(93.94,20.07) v3(94.04,26.11) v3(94.04,18.19) v3(94.12,52.5) v3(94.25,41.58) v3(94.25,36.5) v3(94.2,21.54) v3(94.37,48.31) v3(94.35,6.27) v3(94.45,4.5) v3(94.5,14.78) v3(94.5,3.48) v3(94.68,29.47) v3(94.68,28.38) v3(94.65,27.24) v3(94.68,25.48) v3(94.65,24.38) v3(94.7,23.04) v3(94.73,20.88) v3(94.73,13.97) v3(94.7,13) v3(94.7,12.01) v3(94.7,11.02) v3(94.73,5.33) v3(94.81,22.12) v3(95.03,18.21) v3(95.21,35.71) v3(95.47,14.66) v3(95.44,13.51) v3(95.47,12.62) v3(95.47,11.61) v3(95.47,10.59) v3(95.47,9.58) v3(95.44,8.69) v3(95.47,4.5) v3(95.47,3.48) v3(95.57,41.25) v3(95.52,31.42) v3(95.67,27.24) v3(95.77,49.58) v3(95.77,47.17) v3(95.69,29.47) v3(95.69,28.38) v3(95.8,25.93) v3(95.82,24.94) v3(95.82,21.64) v3(95.92,16.99) v3(95.9,15.98) v3(96.02,23.65) v3(96.02,22.63) v3(96.1,18.26) v3(96.3,10.54) v3(96.48,12.62) v3(96.46,8.71) v3(96.48,7.54) v3(96.48,6.53) v3(96.48,4.5) v3(96.48,3.48) v3(96.56,14.53) v3(96.58,13.67) v3(96.51,11.66) v3(96.63,31.34) v3(96.61,17.48) v3(96.6,16.48) v3(96.6,15.47) v3(96.69,9.53) v3(96.79,41.58) v3(96.79,36.5) v3(96.74,25.65) v3(96.89,24.56) v3(97.07,29.21) v3(97.04,23.65) v3(97.04,22.63) v3(97.04,21.62) v3(96.99,20.6) v3(97.02,19.71) v3(97.04,18.44) v3(97.17,48.31) v3(97.12,0.56) v3(97.35,39.17) v3(97.45,13.64) v3(97.4,12.57) v3(97.55,17.5) v3(97.57,16.43) v3(97.54,15.52) v3(97.55,14.55) v3(97.52,11.63) v3(97.5,8.56) v3(97.5,7.54) v3(97.5,4.5) v3(97.5,3.48) v3(97.5,2.46) v3(97.5,1.45) v3(97.68,10.62) v3(97.7,9.55) v3(97.9,6.27) v3(98.05,41.76) v3(98.06,23.65) v3(98.06,22.63) v3(98.06,21.62) v3(98.06,20.6) v3(98.08,19.69) v3(98.08,18.47) v3(98.15,36.57) v3(98.18,35.36) v3(98.34,8.41) v3(98.44,52.1) v3(98.44,13.67) v3(98.46,12.57) v3(98.56,49.96) v3(98.56,49.07) v3(98.56,47.93) v3(98.56,46.79) v3(98.56,45.64) v3(98.56,44.5) v3(98.56,43.61) v3(98.51,7.54) v3(98.54,4.45) v3(98.51,2.46) v3(98.51,1.45) v3(98.62,17.55) v3(98.69,3.45) v3(98.86,42.67) v3(98.82,33.71) v3(98.82,32.44) v3(99.02,30.45) v3(99.07,23.65) v3(99.07,22.63) v3(99.07,21.62) v3(99.07,20.6) v3(99.17,51.1) v3(99.09,37.79) v3(99.12,35.2) v3(99.1,18.44) v3(99.12,14.61) v3(99.17,12.07) v3(99.12,6.88) v3(99.25,40.36) v3(99.28,28.6) v3(99.23,19.71) v3(99.23,8) v3(99.33,41.58) v3(99.33,39.04) v3(99.33,36.5) v3(99.33,5.89) v3(99.47,26.26) v3(99.76,17.02) v3(99.86,52.12) v3(99.83,31.11) v3(99.83,16.08) v3(99.83,15.21) v3(99.91,49.05) v3(99.91,48.11) v3(100.04,50.34) v3(100.16,46.25) v3(100.16,44.45) v3(100.11,38.1) v3(100.09,23.65) v3(100.09,22.63) v3(100.09,21.62) v3(100.09,20.6) v3(100.13,18.36) v3(100.16,12.75) v3(100.27,42.54) v3(100.27,40.64) v3(100.26,39.39) v3(100.22,37.01) v3(100.24,7.54) v3(100.24,6.53) v3(100.24,5.51) v3(100.24,4.5) v3(100.24,2.46) v3(100.24,1.45) v3(100.37,13.79) v3(100.39,19.76) v3(100.47,11.68) v3(101.08,52.13) v3(101.08,51.12) v3(101.08,50.1) v3(101.08,49.08) v3(101.08,48.07) v3(101.08,47.05) v3(101.08,46.04) v3(101.08,45.02) v3(101.08,44) v3(101.08,42.99) v3(101.08,41.97) v3(101.08,40.96) v3(101.08,39.94) v3(101.08,38.92) v3(101.08,37.91) v3(101.08,36.89) v3(101.08,35.88) v3(101.08,34.86) v3(101.08,33.84) v3(101.08,32.83) v3(101.08,31.81) v3(101.08,30.8) v3(101.08,29.78) v3(101.08,28.76) v3(101.08,27.75) v3(101.08,26.73) v3(101.08,25.72) v3(101.08,24.7) v3(101.05,18.36) v3(101.1,23.65) v3(101.1,22.63) v3(101.1,21.62) v3(101.16,20.32) v3(101.28,16.84) v3(101.26,8.56) v3(101.26,7.54) v3(101.26,6.53) v3(101.26,5.51) v3(101.26,2.46) v3(101.26,1.45) v3(101.33,15.98) v3(101.33,15.11) v3(101.51,17.65) v3(101.54,9.6) v3(101.61,10.59) v3(102.3,52.12) v3(102.3,51.1) v3(102.3,50.09) v3(102.3,49.07) v3(102.3,48.05) v3(102.3,47.04) v3(102.3,46.02) v3(102.3,45.01) v3(102.3,43.99) v3(102.3,42.97) v3(102.3,41.96) v3(102.3,40.94) v3(102.3,39.93) v3(102.3,38.91) v3(102.3,37.89) v3(102.3,36.88) v3(102.3,35.86) v3(102.3,34.85) v3(102.3,33.83) v3(102.3,32.81) v3(102.3,31.8) v3(102.3,30.78) v3(102.3,29.77) v3(102.3,28.75) v3(102.3,27.73) v3(102.3,26.72) v3(102.3,25.7) v3(102.3,24.69) v3(102.3,23.67) v3(102.3,22.65) v3(102.33,21.74) v3(102.45,20.47) v3(102.43,0.58) v3(102.78,7.34) v3(102.78,2.44) v3(102.83,9.78) v3(102.81,8.28) v3(102.83,6.48) v3(102.91,5.59) v3(103.04,1.47) v3(103.14,10.72) v3(103.31,14.66) v3(103.47,20.78) v3(103.39,15.98) v3(103.52,52.12) v3(103.52,51.1) v3(103.52,50.09) v3(103.52,49.07) v3(103.52,48.05) v3(103.52,47.04) v3(103.52,46.02) v3(103.52,45.01) v3(103.52,43.99) v3(103.52,42.97) v3(103.52,41.96) v3(103.52,40.94) v3(103.52,39.93) v3(103.52,38.91) v3(103.52,37.89) v3(103.52,36.88) v3(103.52,35.86) v3(103.52,34.85) v3(103.52,33.83) v3(103.52,32.81) v3(103.52,31.8) v3(103.52,30.78) v3(103.52,29.77) v3(103.52,28.75) v3(103.52,27.73) v3(103.52,26.72) v3(103.52,25.7) v3(103.52,24.69) v3(103.52,23.67) v3(103.52,22.65) v3(103.55,21.74) v3(103.54,18.29) v3(103.57,17.14) v3(104.2,13.79) v3(104.36,11.68) v3(104.46,20.85) v3(104.51,18.34) v3(104.64,52.1) v3(104.64,51.08) v3(104.64,50.06) v3(104.64,49.05) v3(104.64,48.03) v3(104.64,47.02) v3(104.64,46) v3(104.64,44.98) v3(104.64,43.97) v3(104.64,42.95) v3(104.64,41.94) v3(104.64,40.92) v3(104.64,39.9) v3(104.64,38.89) v3(104.64,37.87) v3(104.64,36.86) v3(104.64,35.84) v3(104.64,34.82) v3(104.64,33.81) v3(104.64,32.79) v3(104.64,31.78) v3(104.64,30.76) v3(104.64,29.74) v3(104.64,28.73) v3(104.64,27.71) v3(104.64,26.7) v3(104.64,25.68) v3(104.64,24.66) v3(104.64,23.65) v3(104.64,22.63) v3(104.66,21.72) v3(104.66,12.75) v3(104.74,17.14) v3(104.79,7.54) v3(104.79,6.53) v3(104.79,5.51) v3(104.79,2.46) v3(104.79,1.45) v3(105.24,20.32) v3(105.37,13.59) v3(105.5,18.31) v3(105.65,52.1) v3(105.65,51.08) v3(105.65,50.06) v3(105.65,49.05) v3(105.65,48.03) v3(105.65,47.02) v3(105.65,46) v3(105.65,44.98) v3(105.65,43.97) v3(105.65,42.95) v3(105.65,41.94) v3(105.65,40.92) v3(105.65,39.9) v3(105.65,38.89) v3(105.65,37.87) v3(105.65,36.86) v3(105.65,35.84) v3(105.65,34.82) v3(105.65,33.81) v3(105.65,32.79) v3(105.65,31.78) v3(105.65,30.76) v3(105.65,29.74) v3(105.65,28.73) v3(105.65,27.71) v3(105.65,26.7) v3(105.65,25.68) v3(105.65,24.66) v3(105.65,23.65) v3(105.65,22.63) v3(105.65,21.62) v3(105.75,12.01) v3(105.8,7.54) v3(105.8,6.53) v3(105.8,5.51) v3(105.8,4.5) v3(105.8,3.48) v3(105.8,2.46) v3(105.8,1.45) v3(106.06,17.17) v3(106.08,12.95) v3(106.67,52.1) v3(106.67,51.08) v3(106.67,50.06) v3(106.67,49.05) v3(106.67,48.03) v3(106.67,47.02) v3(106.67,46) v3(106.67,44.98) v3(106.67,43.97) v3(106.67,42.95) v3(106.67,41.94) v3(106.67,40.92) v3(106.67,39.9) v3(106.67,38.89) v3(106.67,37.87) v3(106.67,36.86) v3(106.67,35.84) v3(106.67,34.82) v3(106.67,33.81) v3(106.67,32.79) v3(106.67,31.78) v3(106.67,30.76) v3(106.67,29.74) v3(106.67,28.73) v3(106.67,27.71) v3(106.67,26.7) v3(106.67,25.68) v3(106.67,24.66) v3(106.67,23.65) v3(106.67,22.63) v3(106.67,21.62) v3(106.64,18.31) v3(106.72,20.4) v3(106.85,14.61) v3(106.82,13.64) v3(106.85,11.99) v3(106.82,8.56) v3(106.82,7.54) v3(106.82,6.53) v3(106.82,5.51) v3(106.82,4.5) v3(106.82,3.48) v3(106.82,2.46) v3(106.82,1.45) v3(106.92,16.64) v3(106.92,15.6) v3(106.92,9.98) v3(107.15,17.5) v3(107.68,52.1) v3(107.68,51.08) v3(107.68,50.06) v3(107.68,49.05) v3(107.68,48.03) v3(107.68,47.02) v3(107.68,46) v3(107.68,44.98) v3(107.68,43.97) v3(107.68,42.95) v3(107.68,41.94) v3(107.68,40.92) v3(107.68,39.9) v3(107.68,38.89) v3(107.68,37.87) v3(107.68,36.86) v3(107.68,35.84) v3(107.68,34.82) v3(107.68,33.81) v3(107.68,32.79) v3(107.68,31.78) v3(107.68,30.76) v3(107.68,29.74) v3(107.68,28.73) v3(107.68,27.71) v3(107.68,26.7) v3(107.68,25.68) v3(107.68,24.66) v3(107.68,23.65) v3(107.68,22.63) v3(107.68,21.62) v3(107.66,18.21) v3(107.76,20.45) v3(107.84,16.69) v3(107.84,15.67) v3(107.84,10.59) v3(107.84,9.58) v3(107.84,8.56) v3(107.84,7.54) v3(107.84,6.53) v3(107.84,5.51) v3(107.84,4.5) v3(107.84,3.48) v3(107.84,2.46) v3(107.84,1.45)
